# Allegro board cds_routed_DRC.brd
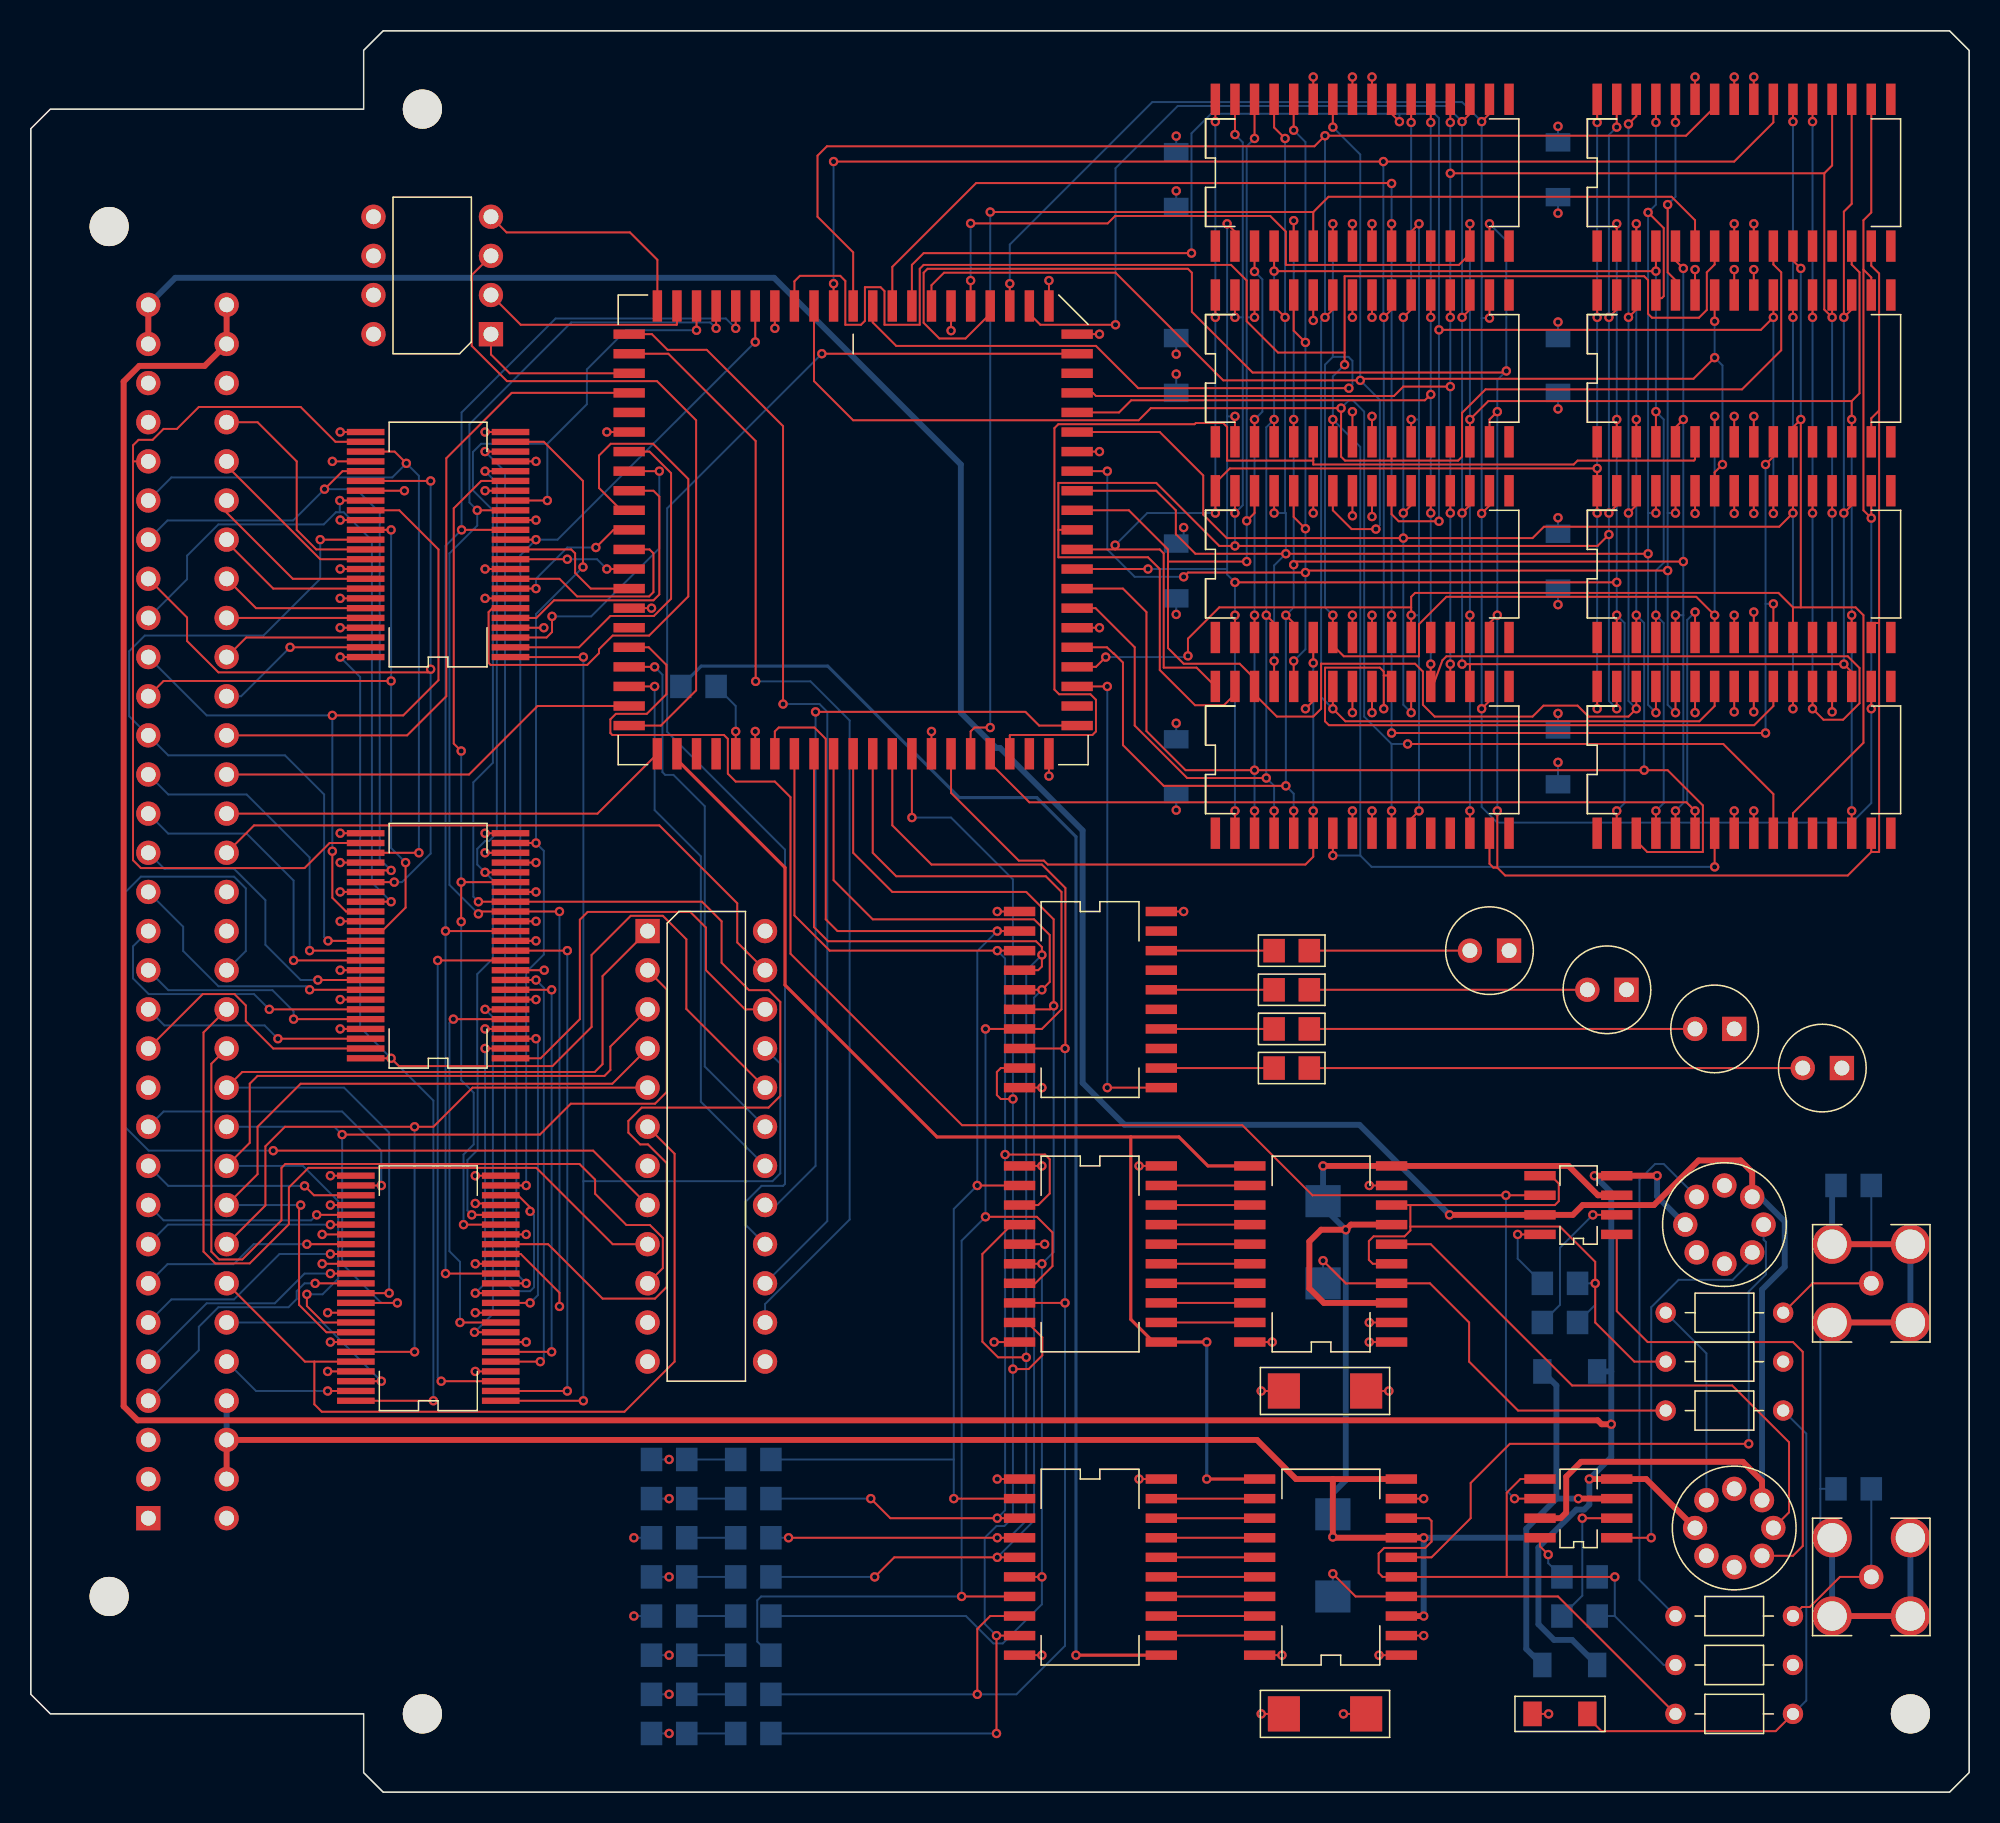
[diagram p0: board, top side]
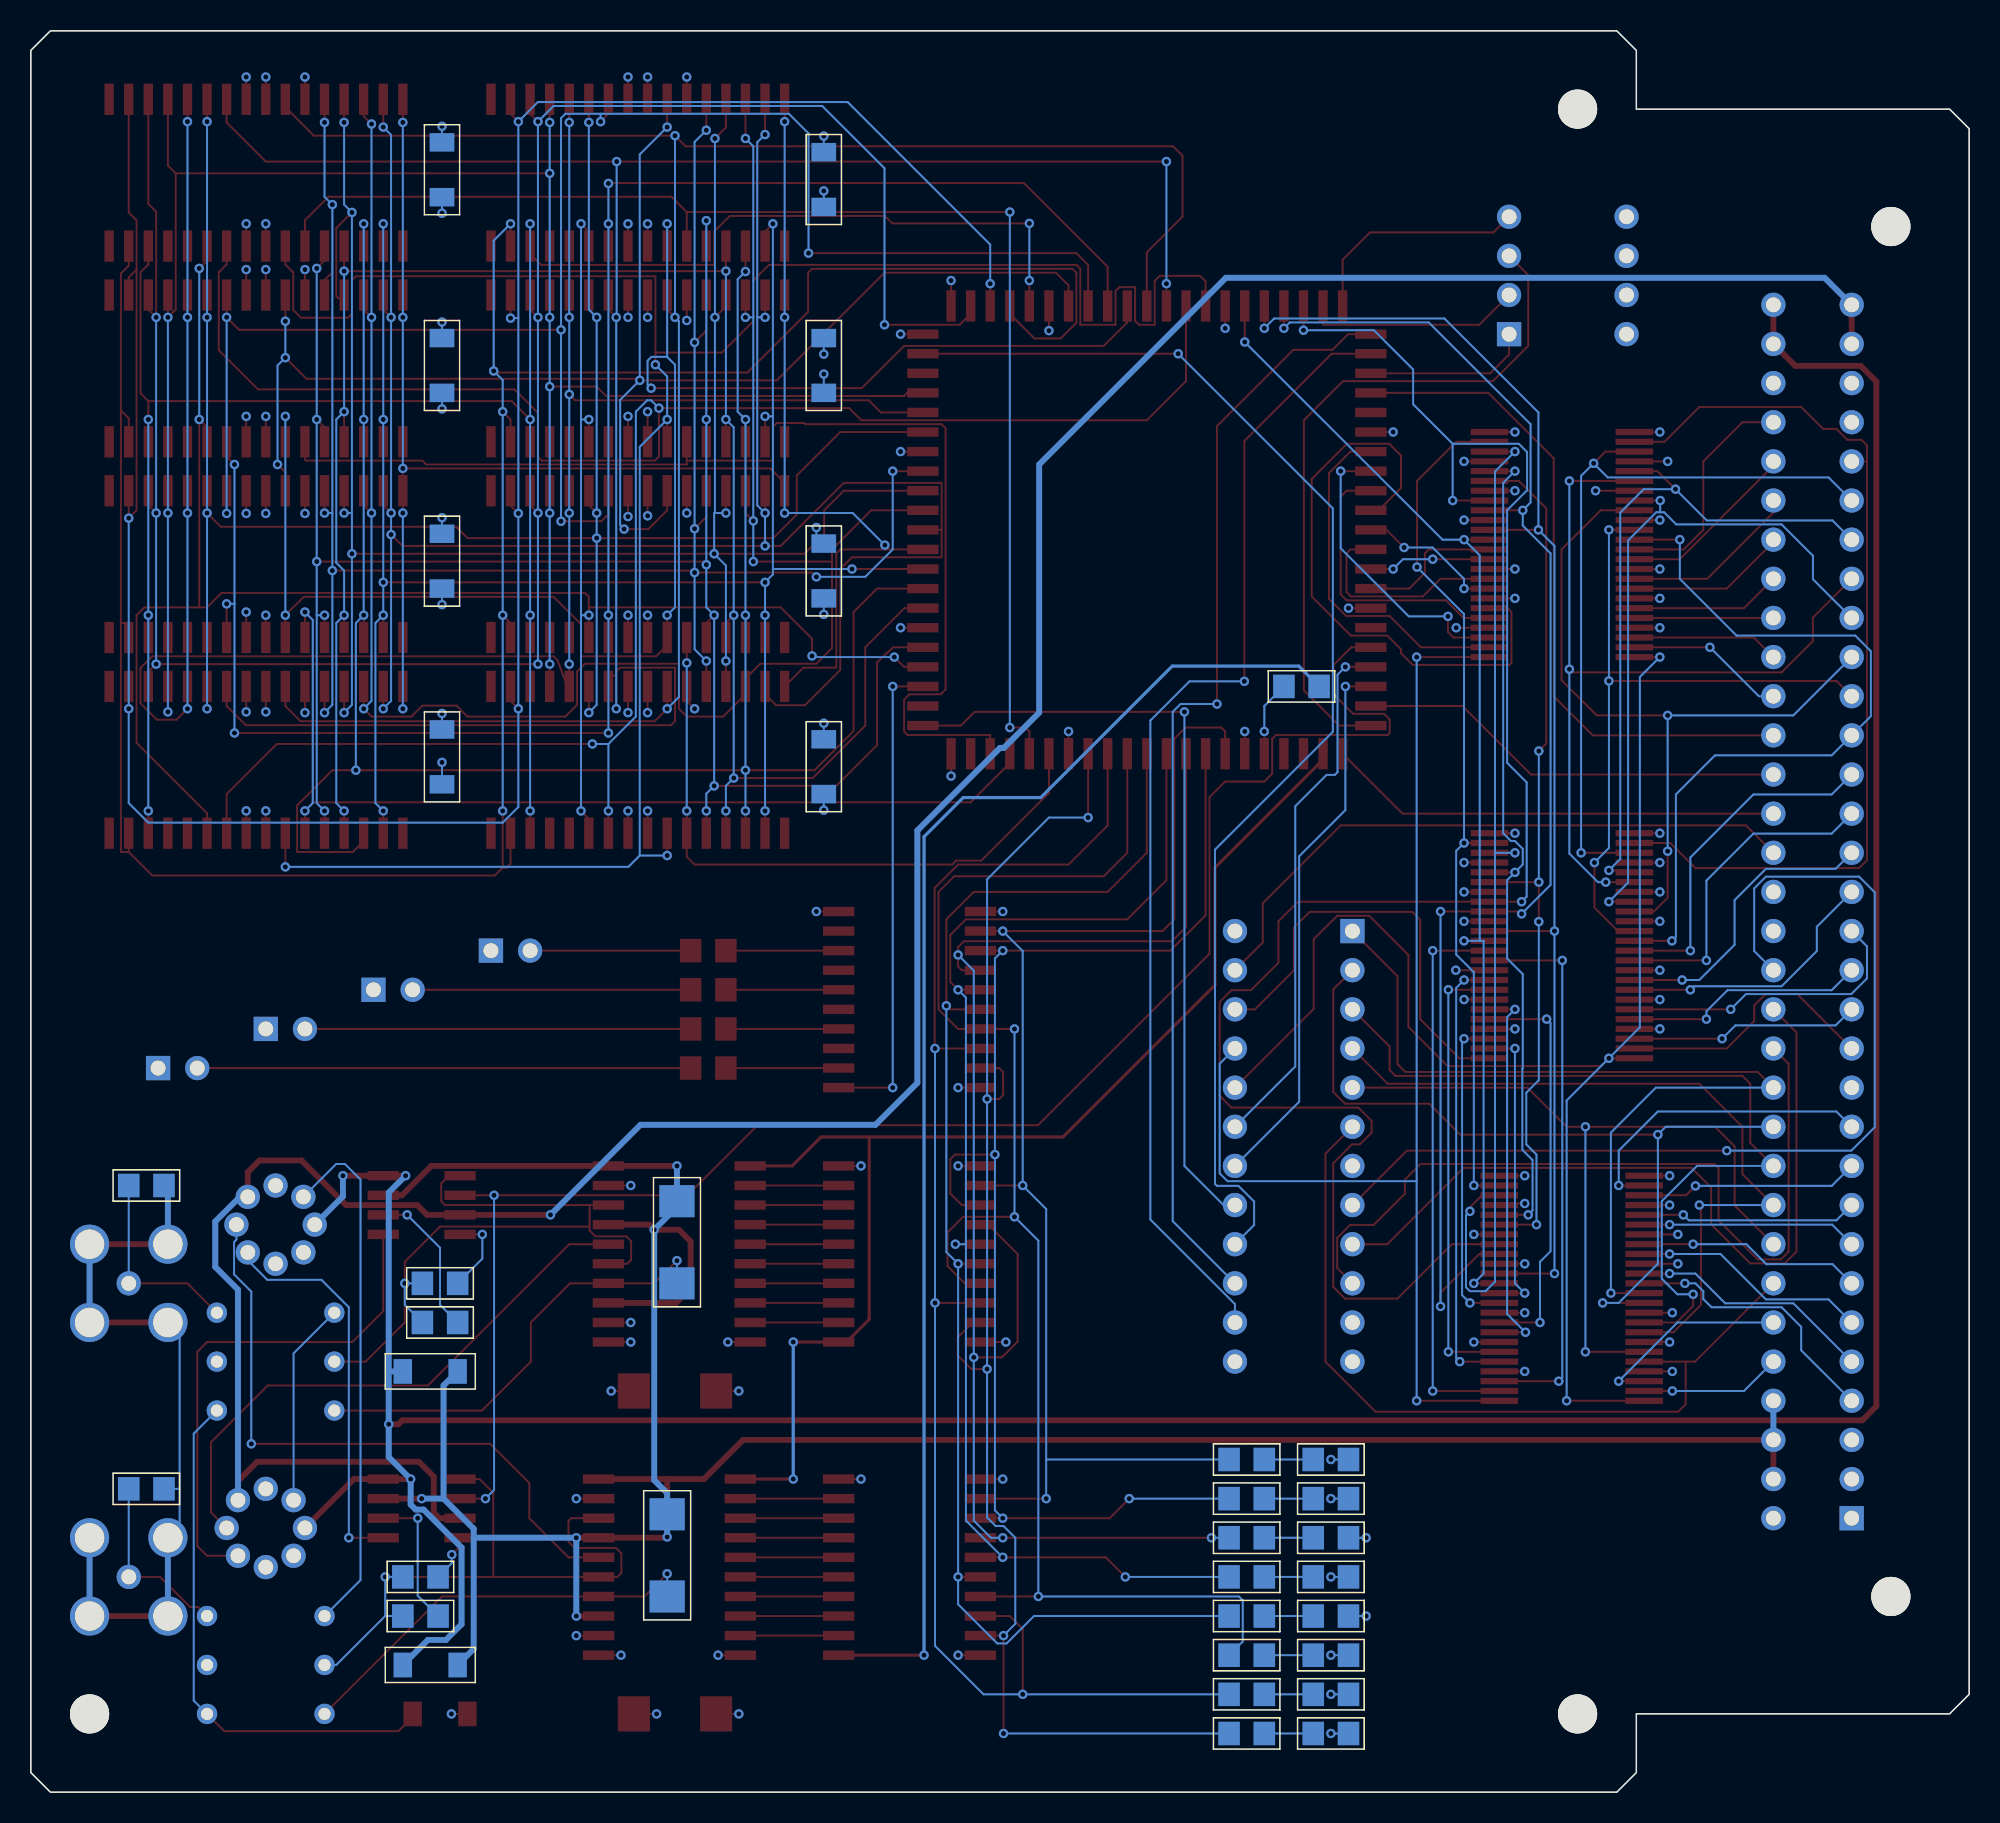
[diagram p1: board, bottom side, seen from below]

Outline 125.73 x 114.3 mm; copper layers: TOP, GND, VCC, BOTTOM. Coordinates in mm from the lower left corner of the outline.

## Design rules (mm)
constraint set DEFAULT: min track width 0.127
net group BNC2: nets BNC2 OUTA
net group BNC3: nets BNC3 OUTB
net group POD_B: nets POD_B+ POD_B-
net group Q1: nets Q0 Q1
net group Q3: nets Q2 Q3
net group Q5: nets Q4 Q5
net group Q7: nets Q6 Q7
net group VCLKC: nets N409523 VCLKC
net group VD0: nets N14855 VD0
net group VD1: nets N14853 VD1
net group VD2: nets N14849 VD2
net group VD3: nets N14843 VD3
net group VD4: nets N15161 VD4
net group VD5: nets N15155 VD5
net group VD6: nets N15151 VD6
net group VD7: nets N15143 VD7
net group N00038_DATA_DAAMP: nets N00038_DATA_DAAMP N00038_DATA_DAAMP0 VREF
net group SYNC: nets VCLKA
nets with their own width: min track width 0.254; nets AGND GND_EARTH V12N V+12

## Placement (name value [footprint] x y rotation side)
C5  47PF  [SM_0805]  119.38 39.37 180 bottom
C6  47PF  [SM_0805]  119.38 19.69 180 bottom
C7  3300  [SM_0805]  42.55 6.35 180 bottom
C8  3300  [SM_0805]  42.55 11.43 180 bottom
C9  3300  [SM_0805]  42.55 16.51 180 bottom
C10  3300  [SM_0805]  42.55 21.59 180 bottom
C11  3300  [SM_0805]  42.55 3.81 180 bottom
C12  3300  [SM_0805]  42.55 8.89 180 bottom
C13  3300  [SM_0805]  42.55 13.97 180 bottom
C14  3300  [SM_0805]  42.55 19.05 180 bottom
C15  0.1uF  [SM_1206]  99.06 103.5 90 bottom
C16  0.1uF  [SM_1206]  99.06 78.11 90 bottom
C17  0.1uF  [SM_1206]  99.06 90.8 90 bottom
C18  0.1uF  [SM_1206]  74.3 102.87 90 bottom
C19  0.1uF  [SM_1206]  99.06 65.41 90 bottom
C20  0.1uF  [SM_1206]  74.3 90.8 90 bottom
C21  0.1uF  [SM_1206]  74.3 77.47 90 bottom
C22  0.1uF  [SM_1206]  74.3 64.77 90 bottom
C23  .01uF  [SMC_6032]  81.28 26.03 0 top
C24  .01uF  [SMC_6032]  83.82 33.02 90 bottom
C25  0.1uF  [SM_1206]  101.6 27.3 180 bottom
C26  .01uF  [SMC_6032]  81.28 5.08 0 top
C27  .01uF  [SMC_6032]  84.45 12.7 90 bottom
C28  0.1uF  [SM_1206]  101.6 8.25 180 bottom
D1  -  [LED]  95.88 54.61 180 top
D2  -  [LED]  103.5 52.07 180 top
D3  -  [LED]  110.49 49.53 180 top
D4  -  [LED]  117.47 46.99 180 top
J1  CON64  [DIN64]  7.62 17.78 0 top
J2  -  [BNC]  119.38 33.02 0 top
J3  -  [BNC]  119.38 13.97 0 top
L1  50  [IND300]  106.04 31.12 0 top
L2  50  [IND300]  106.68 11.43 0 top
L3  50  [IND300]  113.66 24.77 180 top
L4  50  [IND300]  113.66 27.94 180 top
L5  50  [IND300]  114.3 5.08 180 top
L6  50  [IND300]  114.3 8.25 180 top
NOREF  -  [unnamed]  25.4 5.08 0 top
NOREF#2  -  [#2]  -30.48 -55.88 0 top
NOREF#3  -  [#2]  259.08 129.54 0 top
R1  150  [SM_0805]  80.64 54.61 0 top
R2  150  [SM_0805]  80.64 52.07 0 top
R3  150  [SM_0805]  80.64 49.53 0 top
R4  150  [SM_0805]  80.64 46.99 0 top
R5  2K  [SM_0805]  44.45 71.75 180 bottom
R6  10K  [SM_0805]  45.72 6.35 0 bottom
R7  10K  [SM_0805]  45.72 11.43 0 bottom
R8  10K  [SM_0805]  45.72 16.51 0 bottom
R9  10K  [SM_0805]  45.72 21.59 0 bottom
R10  10K  [SM_0805]  45.72 3.81 0 bottom
R11  10K  [SM_0805]  45.72 8.89 0 bottom
R12  10K  [SM_0805]  45.72 13.97 0 bottom
R13  10K  [SM_0805]  45.72 19.05 0 bottom
R14  1/4w  [SM_1206]  100.97 5.08 180 top
R15  100  [SM_0805]  100.33 30.48 180 bottom
R16  100  [SM_0805]  100.33 33.02 180 bottom
R17  100  [SM_0805]  101.6 13.97 180 bottom
R18  100  [SM_0805]  101.6 11.43 180 bottom
U1  FCT16245  [SOIC48]  30.48 25.4 180 top
U2  20L10  [DIP24]  40 55.88 0 top
U3  FCT16245  [SOIC48]  31.11 47.62 180 top
U4  FCT16245  [SOIC48]  31.11 73.66 180 top
U5  EPF8282A_LCC  [PLCC84]  53.34 81.91 180 top
U6  74ACT574  [SOIC20]  64.13 57.15 0 top
U7  EPC1064  [DIP8]  29.84 94.61 180 top
U8  74ACT574  [SOIC20]  64.13 40.64 0 top
U9  74ACT574  [SOIC20]  64.13 20.32 0 top
U10  TC55B4257  [SOIC32]  76.84 62.23 90 top
U11  TC55B4257  [SOIC32]  101.6 100.33 90 top
U12  TC55B4257  [SOIC32]  101.6 62.23 90 top
U13  TC55B4257  [SOIC32]  76.84 87.63 90 top
U14  TC55B4257  [SOIC32]  76.84 74.93 90 top
U15  TC55B4257  [SOIC32]  76.84 100.33 90 top
U16  TC55B4257  [SOIC32]  101.6 74.93 90 top
U17  TC55B4257  [SOIC32]  101.6 87.63 90 top
U18  TLC5602A  [SOIC20]  88.27 29.21 180 top
U19  DG419AK  [SOIC8]  102.87 36.2 180 top
U20  TLE2037A  [TO-99]  110.49 17.14 0 top
U21  TLC5602A  [SOIC20]  88.9 8.89 180 top
U22  TLE2037A  [TO-99]  109.85 36.83 0 top
U23  DG419AK  [SOIC8]  102.87 16.51 180 top

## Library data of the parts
C5 C23 C24 = CAP: room: CHAN1
C6 C26 C27 = CAP: room: CHAN2
C7-C14 = CAP
C15-C22 = CAP NP: room: MEM
C25 = CAP NP: room: CHAN1
C28 = CAP NP: room: CHAN2
D1-D4 = PHOTODIODE
J1 = CON64
J2 = BNC: room: CHAN1
J3 = BNC: room: CHAN2
L1 L3 L4 = INDUCTOR: room: CHAN1
L2 L5 L6 = INDUCTOR: room: CHAN2
R1-R4 = R: room: LED
R5-R13 = R
R14 R17 R18 = R: room: CHAN2
R15 R16 = R: room: CHAN1
U1 U3 U4 = FCT16245
U2 = 20L10: alternate symbols: (T:SOIC24;B:SOIC24_PE)
U5 = EPF8282A/LCC
U6 = 74ACT574: alternate symbols: (TSSOP20;DIP20); room: LED
U7 = EPC1064
U8 = 74ACT574: alternate symbols: (TSSOP20;DIP20); room: CHAN1
U9 = 74ACT574: alternate symbols: (TSSOP20;DIP20); room: CHAN2
U10-U17 = TC55B4257: room: MEM
U18 = TLC5602A: room: CHAN1
U19 = DG419AK: room: CHAN1
U20 = TLE2037A: room: CHAN1
U21 = TLC5602A: room: CHAN2
U22 = TLE2037A: room: CHAN2
U23 = DG419AK: room: CHAN2

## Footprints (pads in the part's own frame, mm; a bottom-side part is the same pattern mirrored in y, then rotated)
BNC
  round 1.575 hole 0.965: 1(0,0)
  round 2.54 hole 1.905: 2(-2.54,2.54) 3(-2.54,-2.54) 4(2.54,2.54) 5(2.54,-2.54)
DIN64
  round 2.54 hole 2.794 unplated: (-2.54,83.82) (-2.54,-5.08)
  rect 1.575x1.575 hole 0.965: 1(0,0)
  round 1.575 hole 0.965: 2(0,2.54) 3(0,5.08) 4(0,7.62) 5(0,10.16) 6(0,12.7) 7(0,15.24) 8(0,17.78) 9(0,20.32) 10(0,22.86) 11(0,25.4) 12(0,27.94) 13(0,30.48) 14(0,33.02) 15(0,35.56) 16(0,38.1) 17(0,40.64) 18(0,43.18) 19(0,45.72) 20(0,48.26) 21(0,50.8) 22(0,53.34) 23(0,55.88) 24(0,58.42) 25(0,60.96) 26(0,63.5) 27(0,66.04) 28(0,68.58) 29(0,71.12) 30(0,73.66) 31(0,76.2) 32(0,78.74) 33(5.08,0) 34(5.08,2.54) 35(5.08,5.08) 36(5.08,7.62) 37(5.08,10.16) 38(5.08,12.7) 39(5.08,15.24) 40(5.08,17.78) 41(5.08,20.32) 42(5.08,22.86) 43(5.08,25.4) 44(5.08,27.94) 45(5.08,30.48) 46(5.08,33.02) 47(5.08,35.56) 48(5.08,38.1) 49(5.08,40.64) 50(5.08,43.18) 51(5.08,45.72) 52(5.08,48.26) 53(5.08,50.8) 54(5.08,53.34) 55(5.08,55.88) 56(5.08,58.42) 57(5.08,60.96) 58(5.08,63.5) 59(5.08,66.04) 60(5.08,68.58) 61(5.08,71.12) 62(5.08,73.66) 63(5.08,76.2) 64(5.08,78.74)
DIP8
  rect 1.575x1.575 hole 0.965: 1(0,0)
  round 1.575 hole 0.965: 2(0,-2.54) 3(0,-5.08) 4(0,-7.62) 5(7.62,-7.62) 6(7.62,-5.08) 7(7.62,-2.54) 8(7.62,0)
DIP24
  rect 1.575x1.575 hole 0.965: 1(0,0)
  round 1.575 hole 0.965: 2(0,-2.54) 3(0,-5.08) 4(0,-7.62) 5(0,-10.16) 6(0,-12.7) 7(0,-15.24) 8(0,-17.78) 9(0,-20.32) 10(0,-22.86) 11(0,-25.4) 12(0,-27.94) 13(7.62,-27.94) 14(7.62,-25.4) 15(7.62,-22.86) 16(7.62,-20.32) 17(7.62,-17.78) 18(7.62,-15.24) 19(7.62,-12.7) 20(7.62,-10.16) 21(7.62,-7.62) 22(7.62,-5.08) 23(7.62,-2.54) 24(7.62,0)
IND300
  round 1.321 hole 0.787: 1(0,0) 2(7.62,0)
LED
  rect 1.575x1.575 hole 0.965: 1(0,0)
  round 1.575 hole 0.965: 2(2.54,0)
PLCC84
  rect 0.61x2.032 smd: 1(0,-14.529) 2(1.27,-14.529) 3(2.54,-14.529) 4(3.81,-14.529) 5(5.08,-14.529) 6(6.35,-14.529) 7(7.62,-14.529) 8(8.89,-14.529) 9(10.16,-14.529) 10(11.43,-14.529) 11(12.7,-14.529) 33(12.7,14.529) 34(11.43,14.529) 35(10.16,14.529) 36(8.89,14.529) 37(7.62,14.529) 38(6.35,14.529) 39(5.08,14.529) 40(3.81,14.529) 41(2.54,14.529) 42(1.27,14.529) 43(0,14.529) 44(-1.27,14.529) 45(-2.54,14.529) 46(-3.81,14.529) 47(-5.08,14.529) 48(-6.35,14.529) 49(-7.62,14.529) 50(-8.89,14.529) 51(-10.16,14.529) 52(-11.43,14.529) 53(-12.7,14.529) 75(-12.7,-14.529) 76(-11.43,-14.529) 77(-10.16,-14.529) 78(-8.89,-14.529) 79(-7.62,-14.529) 80(-6.35,-14.529) 81(-5.08,-14.529) 82(-3.81,-14.529) 83(-2.54,-14.529) 84(-1.27,-14.529)
  rect 2.032x0.61 smd: 12(14.529,-12.7) 13(14.529,-11.43) 14(14.529,-10.16) 15(14.529,-8.89) 16(14.529,-7.62) 17(14.529,-6.35) 18(14.529,-5.08) 19(14.529,-3.81) 20(14.529,-2.54) 21(14.529,-1.27) 22(14.529,0) 23(14.529,1.27) 24(14.529,2.54) 25(14.529,3.81) 26(14.529,5.08) 27(14.529,6.35) 28(14.529,7.62) 29(14.529,8.89) 30(14.529,10.16) 31(14.529,11.43) 32(14.529,12.7) 54(-14.529,12.7) 55(-14.529,11.43) 56(-14.529,10.16) 57(-14.529,8.89) 58(-14.529,7.62) 59(-14.529,6.35) 60(-14.529,5.08) 61(-14.529,3.81) 62(-14.529,2.54) 63(-14.529,1.27) 64(-14.529,0) 65(-14.529,-1.27) 66(-14.529,-2.54) 67(-14.529,-3.81) 68(-14.529,-5.08) 69(-14.529,-6.35) 70(-14.529,-7.62) 71(-14.529,-8.89) 72(-14.529,-10.16) 73(-14.529,-11.43) 74(-14.529,-12.7)
SM_0805
  rect 1.397x1.524 smd: 1(0,0) 2(2.286,0)
SM_1206
  rect 1.194x1.6 smd: 1(0,0) 2(3.556,0)
SMC_6032
  rect 2.083x2.286 smd: 1(0,0) 2(5.334,0)
SOIC8
  rect 2.032x0.61 smd: 1(0,0) 2(0,-1.27) 3(0,-2.54) 4(0,-3.81) 5(4.978,-3.81) 6(4.978,-2.54) 7(4.978,-1.27) 8(4.978,0)
SOIC20
  rect 2.032x0.61 smd: 1(0,0) 2(0,-1.27) 3(0,-2.54) 4(0,-3.81) 5(0,-5.08) 6(0,-6.35) 7(0,-7.62) 8(0,-8.89) 9(0,-10.16) 10(0,-11.43) 11(9.195,-11.43) 12(9.195,-10.16) 13(9.195,-8.89) 14(9.195,-7.62) 15(9.195,-6.35) 16(9.195,-5.08) 17(9.195,-3.81) 18(9.195,-2.54) 19(9.195,-1.27) 20(9.195,0)
SOIC32
  rect 2.032x0.61 smd: 1(0,0) 2(0,-1.27) 3(0,-2.54) 4(0,-3.81) 5(0,-5.08) 6(0,-6.35) 7(0,-7.62) 8(0,-8.89) 9(0,-10.16) 10(0,-11.43) 11(0,-12.7) 12(0,-13.97) 13(0,-15.24) 14(0,-16.51) 15(0,-17.78) 16(0,-19.05) 17(9.525,-19.05) 18(9.525,-17.78) 19(9.525,-16.51) 20(9.525,-15.24) 21(9.525,-13.97) 22(9.525,-12.7) 23(9.525,-11.43) 24(9.525,-10.16) 25(9.525,-8.89) 26(9.525,-7.62) 27(9.525,-6.35) 28(9.525,-5.08) 29(9.525,-3.81) 30(9.525,-2.54) 31(9.525,-1.27) 32(9.525,0)
SOIC48
  rect 2.438x0.406 smd: 1(0,0) 2(0,-0.635) 3(0,-1.27) 4(0,-1.905) 5(0,-2.54) 6(0,-3.175) 7(0,-3.81) 8(0,-4.445) 9(0,-5.08) 10(0,-5.715) 11(0,-6.35) 12(0,-6.985) 13(0,-7.62) 14(0,-8.255) 15(0,-8.89) 16(0,-9.525) 17(0,-10.16) 18(0,-10.795) 19(0,-11.43) 20(0,-12.065) 21(0,-12.7) 22(0,-13.335) 23(0,-13.97) 24(0,-14.605) 25(9.398,-14.605) 26(9.398,-13.97) 27(9.398,-13.335) 28(9.398,-12.7) 29(9.398,-12.065) 30(9.398,-11.43) 31(9.398,-10.795) 32(9.398,-10.16) 33(9.398,-9.525) 34(9.398,-8.89) 35(9.398,-8.255) 36(9.398,-7.62) 37(9.398,-6.985) 38(9.398,-6.35) 39(9.398,-5.715) 40(9.398,-5.08) 41(9.398,-4.445) 42(9.398,-3.81) 43(9.398,-3.175) 44(9.398,-2.54) 45(9.398,-1.905) 46(9.398,-1.27) 47(9.398,-0.635) 48(9.398,0)
TO-99
  round 1.575 hole 0.965: 1(0,-2.54) 2(1.803,-1.803) 3(2.54,0) 4(1.803,1.803) 5(0,2.54) 6(-1.803,1.803) 7(-2.54,0) 8(-1.803,-1.803)
unnamed
  round 2.54 hole 2.794 unplated: (0,104.14) (0,0) (96.52,0)

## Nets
AGND: C24.2 C25.2 C27.2 C28.2 J1.34 J1.35 J1.36 U18.3 U18.7 U18.10 U19.3 U21.3 U21.7 U21.10 U23.3
GND: C7.2 C8.2 C9.2 C10.2 C11.2 C12.2 C13.2 C14.2 C15.2 C16.2 C17.2 C18.2 C19.2 C20.2 C21.2 C22.2 C23.2 C26.2 J1.1 J1.2 J1.3 J1.33 R14.2 U1.4 U1.10 U1.15 U1.21 U1.24 U1.25(\G\\\) U1.28 U1.34 U1.39 U1.45 U2.11 U2.12 U2.13 U3.4 U3.10 U3.15 U3.21 U3.24 U3.25(\G\\\) U3.28 U3.34 U3.39 U3.45 U4.4 U4.10 U4.15 U4.21 U4.24 U4.25(\G\\\) U4.28 U4.34 U4.39 U4.45 U5.5 U5.26 U5.47 U5.53 U5.68 U5.74 U5.75 U6.1 U6.10 U7.5 U8.1 U8.10 U9.1 U9.10 U10.9 U10.25 U10.27 U11.9 U11.25 U11.27 U12.9 U12.25 U12.27 U13.9 U13.25 U13.27 U14.9 U14.25 U14.27 U15.9 U15.25 U15.27 U16.9 U16.25 U16.27 U17.9 U17.25 U17.27 U18.1 U18.20 U21.1 U21.20
GND_EARTH: C5.2 C6.2 J2.2 J2.3 J2.4 J2.5(\GND5\) J3.2 J3.3 J3.4 J3.5(\GND5\)
V12N: J1.31 J1.32 U19.7 U20.4(\V-\) U22.4(\V-\) U23.7
VCC: C15.1 C16.1 C17.1 C18.1 C19.1 C20.1 C21.1 C22.1 C23.1 C26.1 D1.1 D2.1 D3.1 D4.1 J1.29 J1.30 J1.62 L4.1 L6.1 U1.7 U1.18 U1.31 U1.42 U2.24(\VCC\) U3.7 U3.18 U3.31 U3.42 U4.7 U4.18 U4.31 U4.42 U5.17 U5.38 U5.59 U5.80 U6.20 U7.7 U7.8 U8.20 U9.20 U10.8 U10.24 U11.8 U11.24 U12.8 U12.24 U13.8 U13.24 U14.8 U14.24 U15.8 U15.24 U16.8 U16.24 U17.8 U17.24 U18.2 U18.9(\VD2\) U21.2 U21.9(\VD2\)
A0: J1.54 U4.47
A1: J1.55 U4.46
A2: J1.56 U4.44
A3: J1.57 U4.43
A4: J1.58 U4.41
A5: J1.59 U4.40
A6: J1.60 U4.38
A7: J1.61 U4.37
A8: J1.13 U3.47
A9: J1.14 U3.46
A10: J1.15 U3.44
A11: J1.16 U3.43
A12: J1.17 U3.41
A13: J1.18 U3.40
A14: J1.19 U3.38
A15: J1.20 U3.37
A16: J1.37 U1.47
A17: J1.38 U1.46
A18: J1.39 U1.44 U2.6
A19: J1.40 U1.43 U2.5
A20: J1.41 U1.41 U2.4
A21: J1.42 U1.40 U2.3
A22: J1.43 U1.38 U2.2
A23: J1.44 U1.37 U2.1
AEN: J1.47 U2.8
BA0: U1.13 U3.13 U4.13 U5.6
BA1: U1.14 U3.14 U4.14 U5.7
BA2: U1.16 U3.16 U4.16 U5.8
BA3: U1.17 U3.17 U4.17 U5.9
BA4: U1.19 U3.19 U4.19
BA5: U1.20 U3.20 U4.20
BA6: U1.22 U3.22 U4.22
BA7: U1.23 U3.23 U4.23
BD0: U4.12 U5.25
BD1: U4.11 U5.24
BD2: U4.9 U5.23
BD3: U4.8 U5.22
BD4: U4.6 U5.21
BD5: U4.5 U5.20
BD6: U4.3 U5.19
BD7: U4.2 U5.18
BD8: U1.12 U3.2
BD9: U1.11 U3.3
BD10: U1.9 U3.5
BD11: U1.8 U3.6
BD12: U1.6 U3.8
BD13: U1.5 U3.9
BD14: U1.3 U3.11
BD15: U1.2 U3.12
BNC2: C5.1 J2.1 L1.2
BNC3: C6.1 J3.1 L2.2
BRD: U2.16 U5.73
BRESET: U2.15 U5.12
BWR: U2.17 U5.54
D0: J1.28 U3.26 U4.26
D1: J1.27 U3.27 U4.27
D2: J1.26 U3.29 U4.29
D3: J1.25 U3.30 U4.30
D4: J1.24 U3.32 U4.32
D5: J1.23 U3.33 U4.33
D6: J1.22 U3.35 U4.35
D7: J1.21 U3.36 U4.36
DATA: U5.14 U7.1
DCLK: U5.10 U7.2
DDIR: U1.48 U2.20 U3.48 U4.48
DEN: U1.1 U2.21 U4.1
DHEN: U2.22 U3.1
FPGA: U2.18 U5.30
GAIN: U5.28 U19.6 U23.6
HS: U2.19 U5.29
MCLK: J1.52 U5.31
MRD: J1.46 U2.9
MWR: J1.45 U2.10
N00036_DATA_DAAMP: L4.2 R15.1 R16.1 U18.5 U18.8 U19.5(\VL\)
N00036_DATA_DAAMP0: L6.2 R17.1 R18.1 U21.5 U21.8 U23.5(\VL\)
N00038_DATA_DAAMP: C24.1 L3.2 U18.4
N00038_DATA_DAAMP0: C27.1 L5.2 U21.4
N00044_DATA_DAAMP: U19.1 U20.2
N00044_DATA_DAAMP0: U22.2 U23.1
N00060_DATA_DAAMP: U18.6 U20.3
N00060_DATA_DAAMP0: U21.6 U22.3
N282866_DATA_DAAMP: R16.2 U19.8
N282866_DATA_DAAMP0: R17.2 U23.8
N282912_DATA_DAAMP: R15.2 U19.2
N282912_DATA_DAAMP0: R18.2 U23.2
NCS: U5.11 U7.4
OE: U5.32 U7.3(\OE\)
OUTA: L1.1 U20.6
OUTB: L2.1 U22.6
POD_A+: J1.11 U1.26
POD_A-: J1.10 U1.27
POD_B+: J1.9 U1.29
POD_B-: J1.8 U1.30
POD_C+: J1.7 U1.32
POD_C-: J1.6 U1.33
POD_D+: J1.5 U1.35
POD_D-: J1.4 U1.36
Q0: R4.1 U6.12(\Q8\)
Q1: D4.2(\CATHODE\) R4.2
Q2: R3.1 U6.14
Q3: D3.2(\CATHODE\) R3.2
Q4: R2.1 U6.16
Q5: D2.2(\CATHODE\) R2.2
Q6: R1.1 U6.18
Q7: D1.2(\CATHODE\) R1.2
RA0: U5.58 U10.5 U11.5 U12.5 U13.5 U14.5 U15.5 U16.5 U17.5
RA1: U5.60 U10.4 U11.4 U12.4 U13.4 U14.4 U15.4 U16.4 U17.4
RA2: U5.61 U10.3 U11.3 U12.3 U13.3 U14.3 U15.3 U16.3 U17.3
RA3: U5.62 U10.2 U11.2 U12.2 U13.2 U14.2 U15.2 U16.2 U17.2
RA4: U5.63 U10.32 U11.32 U12.32 U13.32 U14.32 U15.32 U16.32 U17.32
RA5: U5.64 U10.31 U11.31 U12.31 U13.31 U14.31 U15.31 U16.31 U17.31
RA6: U5.65 U10.30 U11.30 U12.30 U13.30 U14.30 U15.30 U16.30 U17.30
RA7: U5.66 U10.29 U11.29 U12.29 U13.29 U14.29 U15.29 U16.29 U17.29
RA8: U5.67 U10.28 U11.28 U12.28 U13.28 U14.28 U15.28 U16.28 U17.28
RA9: U5.69 U10.22 U11.22 U12.22 U13.22 U14.22 U15.22 U16.22 U17.22
RA10: U5.70 U10.21 U11.21 U12.21 U13.21 U14.21 U15.21 U16.21 U17.21
RA11: U5.71 U10.20 U11.20 U12.20 U13.20 U14.20 U15.20 U16.20 U17.20
RA12: U5.76 U10.19 U11.19 U12.19 U13.19 U14.19 U15.19 U16.19 U17.19
RA13: U5.77 U10.18 U11.18 U12.18 U13.18 U14.18 U15.18 U16.18 U17.18
RA14: U5.78 U10.15 U11.15 U12.15 U13.15 U14.15 U15.15 U16.15 U17.15
RA15: U5.79 U10.14 U11.14 U12.14 U13.14 U14.14 U15.14 U16.14 U17.14
RCS0: U5.48 U10.6 U14.6
RCS1: U5.49 U11.6 U15.6
RCS2: U5.50 U12.6 U16.6
RCS3: U5.51 U13.6 U17.6
RD0: U5.81 U14.26 U15.26 U16.26 U17.26
RD1: U5.82 U14.23 U15.23 U16.23 U17.23
RD2: U5.83 U14.10 U15.10 U16.10 U17.10
RD3: U5.84 U14.7 U15.7 U16.7 U17.7
RD4: U5.1 U10.26 U11.26 U12.26 U13.26
RD5: U5.2 U10.23 U11.23 U12.23 U13.23
RD6: U5.3 U10.10 U11.10 U12.10 U13.10
RD7: U5.4 U10.7 U11.7 U12.7 U13.7
RDY: J1.50 U2.23
RESET: J1.53 U5.15
RWE: U5.57 U10.11(\W\\E\\\) U11.11(\W\\E\\\) U12.11(\W\\E\\\) U13.11(\W\\E\\\) U14.11(\W\\E\\\) U15.11(\W\\E\\\) U16.11(\W\\E\\\) U17.11(\W\\E\\\)
SEL: U2.14 U5.13
V+12: C25.1 C28.1 J1.63 J1.64 U19.4 U20.7 U22.7 U23.4
VCLKA: U5.34 U8.11 U18.11 U21.11
VCLKC: R5.2 U9.11
VD0: R9.2 U5.39 U6.2 U8.2 U9.2
VD1: R13.2 U5.40 U6.3 U8.3 U9.3
VD2: R8.2 U5.41 U6.4 U8.4 U9.4
VD3: R12.2 U5.42 U6.5 U8.5 U9.5
VD4: R7.2 U5.43 U6.6 U8.6 U9.6
VD5: R11.2 U5.44 U6.7 U8.7 U9.7
VD6: R6.2 U5.45 U6.8 U8.8 U9.8
VD7: R10.2 U5.46(\VD7\) U6.9 U8.9 U9.9
VREF: L3.1 L5.1 R14.1
WAIT: J1.51 U5.33
WSTAT: U5.56 U6.11
N14843: C13.1 R12.1
N14849: C9.1 R8.1
N14853: C14.1 R13.1
N14855: C10.1 R9.1
N15143: C11.1 R10.1
N15151: C7.1 R6.1
N15155: C12.1 R11.1
N15161: C8.1 R7.1
N58063: U8.19 U18.12
N58118: U8.18 U18.13
N58173: U8.17 U18.14
N58228: U8.16 U18.15
N58283: U8.15 U18.16
N58338: U8.14 U18.17
N58393: U8.13 U18.18
N58448: U8.12(\Q8\) U18.19
N58834: U9.19 U21.12
N58889: U9.18 U21.13
N58944: U9.17 U21.14
N58999: U9.16 U21.15
N59054: U9.15 U21.16
N59109: U9.14 U21.17
N59164: U9.13 U21.18
N59219: U9.12(\Q8\) U21.19
N409523: R5.1 U5.37

Pads without a net: J1 12 48 49; U2 7; U5 16 27 35 36 52 55 72; U6 13 15 17 19; U7 6; U10 1 12 13 16 17; U11 1 12 13 16 17; U12 1 12 13 16 17; U13 1 12 13 16 17; U14 1 12 13 16 17; U15 1 12 13 16 17; U16 1 12 13 16 17; U17 1 12 13 16 17; U20 1 5 8; U22 1 5 8

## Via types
v1: diameter 0.61, hole 0.33, TOP to BOTTOM, 498 vias

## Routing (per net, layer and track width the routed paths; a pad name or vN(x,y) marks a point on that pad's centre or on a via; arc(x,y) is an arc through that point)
AGND: length 189.2
  TOP w0.381: U18.7 85.62,36.83 v1(85.29,36.5) 83.69,36.5 82.93,35.74 82.93,32.69 83.87,31.75 U18.3 ; 84.45,20.32 82.07,20.32 79.53,22.86 J1.35 J1.34 ; 84.45,20.32 U21.10 ; 84.45,20.32 v1(84.45,16.56) 84.51,16.51 U21.7 v1(90.35,16.51) ; U19.3 101.65,38.73 99.75,40.64 U18.10 v1(83.82,40.64) ; U21.3 v1(90.35,11.43) ; U23.3 v1(100.38,19.05)
  BOTTOM w0.381: C28.2 97,9.3 97,16.51 ; 98.96,19.05 97,17.09 97,16.51 ; 98.96,19.05 98.96,26.39 C25.2 ; 98.96,19.05 v1(100.38,19.05) ; J1.36 J1.35 ; v1(83.82,40.64) C24.2 83.82,37.97 v1(85.29,36.5) 85.29,20.24 84.45,19.41 C27.2 v1(84.45,16.56) ; v1(90.35,11.43) v1(90.35,16.51) 97,16.51
GND: length 135.8
  TOP w0.127: U5.5 v1(48.26,95) ; U18.1 v1(86.82,29.21) ; C26.2 v1(85.14,5.08) ; U1.15 v1(28.83,34.29) ; 21.72,86.36 v1(19.56,86.36) ; 21.72,53.34 v1(20.07,53.34) ; 21.72,88.27 v1(20.07,88.27) ; R14.2 v1(98.45,5.08) ; 83.19,71.75 83.19,70.82 v1(82.68,70.31) ; U1.4 v1(28.83,27.3) ; U16.27 v1(107.95,82.98) ; U4.15 v1(32.77,82.55) ; U3.10 v1(33.3,53.34) ; U1.24 v1(28.83,40) ; 21.72,82.55 v1(20.07,82.55) ; U13.25 v1(85.72,95.71) ; U21.20 v1(81.15,8.89) ; U1.45 v1(19.25,27.3) ; 83.19,97.16 v1(83.19,95.5) ; U17.9 v1(111.76,89.28) ; U6.1 v1(62.69,57.15) ; U1.34 v1(18.9,34.29) ; U17.25 v1(110.49,98.81) ; U21.1 v1(87.45,8.89) ; U1.10 v1(28.83,31.12) ; 21.72,62.23 v1(20.07,62.23) ; U4.21 v1(32.77,86.36) ; U10.9 v1(87,63.68) ; 67.87,87 v1(69.32,87) ; 83.19,109.86 v1(83.19,111.3) ; U12.25 v1(110.49,70.1) ; U8.10 v1(62.48,29.21) ; U3.15 v1(32.77,56.52) ; 21.72,79.38 v1(20.07,79.38) ; 21.72,60.32 v1(20.07,60.32) ; U14.25 v1(85.72,82.83) ; U12.9 v1(111.76,63.68) ; U1.39 v1(19.25,31.12) ; U17.27 v1(107.95,98.81) ; U6.10 v1(65.58,45.72) ; C23.2 v1(88.09,26.03) ; U5.47 v1(58.42,68.83) ; U5.26 v1(40.26,76.83) ; U15.25 v1(85.72,111.3) ; U12.27 v1(107.95,70.05) ; 83.19,84.45 v1(83.19,83.01) ; U5.74 v1(69.32,94.61) ; U9.10 v1(65.58,8.89) ; U10.25 v1(85.72,70.05) ; v1(28.83,38.2) 30.38,38.2 U1.21 ; U5.53 v1(66.04,65.94) ; U13.9 v1(87,89.28) ; U1.28 v1(19.43,38.1) ; U4.10 v1(29.46,79.38) ; U16.9 v1(111.76,76.58) ; U9.1 v1(62.69,20.32) ; U11.27 v1(107.95,111.3) ; U15.9 v1(87,101.78) ; U1.25 v1(19.43,40) ; U11.25 v1(110.49,111.3) ; U3.24 v1(29.46,62.23) ; U8.1 v1(65.58,40.64) ; U18.20 v1(80.52,29.21) ; U4.4 v1(33.27,75.56) ; U14.9 v1(87,76.38) ; U16.25 v1(110.49,82.98) ; 31.11,60.32 v1(32.77,60.32) ; 21.72,56.52 v1(20.07,56.52) ; U5.75 v1(66.04,98.09) ; U11.9 v1(111.76,101.78) ; 21.72,49.53 v1(20.07,49.53) ; 21.72,75.56 v1(20.07,75.56) ; U3.4 v1(29.46,49.53) ; U4.24 v1(29.46,88.27)
  BOTTOM w0.127: C7.2 v1(41.4,6.35) ; C21.2 74.78,81.51 v1(74.78,82.07) ; C10.2 v1(41.4,21.59) ; C22.2 v1(74.3,69.37) ; C19.2 v1(99.06,70) ; C20.2 v1(74.3,93.32) ; C15.2 v1(99.06,108.1) ; C14.2 v1(41.4,19.05) ; C9.2 v1(39.12,16.51) ; C16.2 v1(99.06,82.7) ; C11.2 v1(41.4,3.81) ; C17.2 v1(99.06,95.4) ; C12.2 v1(41.4,8.89) ; C13.2 v1(41.4,13.97) ; C18.2 v1(74.3,107.47) ; C8.2 v1(39.12,11.43)
GND_EARTH: length 50
  TOP w0.381: J3.3 J3.5 ; J2.4 J2.2 ; J2.3 J2.5
  BOTTOM w0.127: J3.2 116.08,17.27 116.08,19.69 ; 116.08,19.69 C6.2 ; 116.08,19.69 116.08,29.72 J2.3
  BOTTOM w0.381: J3.3 J3.2 ; J2.2 116.84,39.12 C5.2 ; J2.4 J2.5 ; J3.4 J3.5
V12N: length 195.4
  TOP w0.381: U22.4 111.66,40.23 110.9,41 108.18,41 105.28,38.1 100.66,38.1 100.03,37.46 U19.7 v1(92.02,37.46) ; J1.31 J1.32 ; U20.4 112.29,20.19 111.05,21.44 100.56,21.44 99.59,20.47 99.59,18.15 99.23,17.78 U23.7
  BOTTOM w0.381: J1.32 9.37,98.27 48.21,98.27 60.32,86.16 60.32,70.05 62.61,67.77 62.87,67.77 68.22,62.41 68.22,46.02 70.94,43.31 86.18,43.31 v1(92.02,37.46) ; U20.4 112.29,32.61 113.77,34.09 113.77,37.03 112.17,38.63 U22.4
VCC: length 73.9
  TOP w0.127: U10.8 v1(85.72,63.68) ; U1.31 v1(18.9,36.2) ; U1.18 v1(32.13,36.2) ; U5.38 v1(46.99,68.83) ; C26.1 v1(79.81,5.08) ; U12.8 v1(110.49,63.68) ; U13.8 v1(85.72,89.59) ; U11.24 v1(111.76,111.3) ; U8.20 v1(71.88,40.64) ; U9.20 v1(71.88,20.32) ; U14.24 v1(87,82.78) ; U1.42 v1(19.43,29.21) ; U17.24 v1(111.76,98.81) ; U4.18 v1(29.46,84.45) ; U14.8 v1(85.72,76.38) ; U15.8 v1(85.72,101.78) ; U16.8 v1(110.49,76.38) ; U16.24 v1(111.76,82.98) ; U18.9 v1(86.82,39.37) ; 21.72,77.47 v1(20.07,77.47) ; U21.9 v1(90.35,19.05) ; 21.72,51.43 v1(20.07,51.43) ; U3.18 v1(32.77,58.42) ; U17.8 v1(110.49,89.28) ; C23.1 v1(79.81,26.03) ; U11.8 v1(110.49,101.78) ; U10.24 v1(87,70.05) ; U15.24 v1(87,111.3) ; U6.20 v1(74.78,57.15) ; U4.7 v1(29.46,77.47) ; 21.72,84.45 v1(24.23,84.45) ; U5.17 v1(37.36,88.27) ; U13.24 v1(87,95.71) ; U3.7 v1(32.77,51.43) ; 21.72,58.42 v1(20.07,58.42) ; U1.7 v1(32.13,29.21) ; U5.80 v1(59.69,94.84) ; U18.2 v1(86.82,30.48) ; U5.59 v1(69.32,75.56) ; U21.2 v1(90.35,10.16) ; U12.24 v1(111.76,70.1)
  BOTTOM w0.127: C15.1 v1(99.06,102.46) ; C16.1 v1(99.06,77.06) ; C18.1 v1(74.3,103.91) ; C22.1 v1(74.3,63.73) ; C21.1 v1(74.3,76.43) ; C19.1 v1(99.06,66.83) ; C20.1 v1(74.3,92.02) ; C17.1 v1(99.06,89.76)
A0: length 10.3
  TOP w0.127: U4.47 v1(16.81,74.3)
  BOTTOM w0.127: J1.54 13.64,71.12 v1(16.81,74.3)
A1: length 9.5
  TOP w0.127: J1.55 13.97,74.93 U4.46
A2: length 9
  TOP w0.127: 21.72,76.2 J1.56
A3: length 9.8
  TOP w0.127: 21.72,76.83 14.6,76.83 J1.57
A4: length 10.4
  TOP w0.127: 21.72,78.11 15.72,78.11 12.7,81.13 J1.58
A5: length 11.6
  TOP w0.127: J1.59 12.7,83.03 16.99,78.74 21.72,78.74
A6: length 11.8
  TOP w0.127: J1.60 12.7,86.08 18.77,80.01 21.72,80.01
A7: length 15
  TOP w0.127: J1.61 14.71,88.9 17.25,86.36 17.25,81.91 18.52,80.64 21.72,80.64
A8: length 17.6
  TOP w0.127: J1.13 11.15,51.79 13.21,51.79 13.94,51.05 13.94,50.04 15.72,48.26 U3.47
A9: length 14.9
  TOP w0.127: U3.46 v1(16.03,48.89)
  BOTTOM w0.127: v1(16.03,48.89) 15.16,49.76 8.66,49.76 J1.14
A10: length 15.7
  TOP w0.127: 21.72,50.16 v1(17.04,50.16)
  BOTTOM w0.127: J1.15 8.92,52.04 15.67,52.04 17.04,50.67 v1(17.04,50.16)
A11: length 19.4
  TOP w0.127: 21.72,50.8 v1(15.47,50.8)
  BOTTOM w0.127: v1(15.47,50.8) 14.48,51.79 7.65,51.79 6.63,52.81 6.63,54.89 J1.16
A12: length 17.6
  TOP w0.127: 21.72,52.07 v1(18.08,52.07)
  BOTTOM w0.127: J1.17 9.88,56.16 9.88,54.58 12.17,52.3 17.86,52.3 v1(18.08,52.07)
A13: length 19.2
  TOP w0.127: 21.72,52.7 v1(18.62,52.7)
  BOTTOM w0.127: J1.18 8.66,59.92 13.18,59.92 15.21,57.89 15.21,54.99 17.5,52.7 v1(18.62,52.7)
A14: length 21.1
  TOP w0.127: 21.72,53.98 v1(17.04,53.98)
  BOTTOM w0.127: J1.19 8.92,62.2 14,62.2 17.04,59.16 v1(17.04,53.98)
A15: length 22.4
  TOP w0.127: 21.72,54.61 v1(18.08,54.61)
  BOTTOM w0.127: v1(18.08,54.61) 18.08,60.66 14,64.74 8.92,64.74 J1.20
A16: length 9.2
  TOP w0.127: U1.47 v1(19.25,26.03)
  BOTTOM w0.127: J1.37 14.6,26.03 v1(19.25,26.03)
A17: length 13.3
  TOP w0.127: U1.46 v1(22.73,26.67)
  BOTTOM w0.127: v1(22.73,26.67) 18.92,30.48 J1.38
A18: length 54.1
  TOP w0.127: U2.6 41.76,41.43 41.76,27.94 38.51,24.69 18.87,24.69 18.39,25.17 18.39,27.94 ; 18.39,27.94 U1.44 ; 18.39,27.94 17.78,27.94 J1.39
A19: length 52.2
  TOP w0.127: U1.43 v1(24.89,28.58) ; J1.40 15.21,38.07 15.21,41.91 16.48,43.18 v1(24.89,43.18) 26.11,43.18 28.65,45.72 U2.5
  BOTTOM w0.127: v1(24.89,28.58) v1(24.89,43.18)
A20: length 49.1
  TOP w0.127: U1.41 19.18,29.84 17.4,31.62 17.4,38 v1(17.5,38.1) ; U2.4 37.72,45.97 17.5,45.97 14.71,43.18 14.71,40.11 J1.41
  BOTTOM w0.127: v1(17.5,38.1) J1.41
A21: length 54.7
  TOP w0.127: U1.40 18.97,30.48 17.91,31.55 v1(17.91,32.31) ; U2.3 37.59,48.39 37.59,46.86 37.21,46.48 14.71,46.48 14.2,45.97 14.2,42.14 J1.42
  BOTTOM w0.127: v1(17.91,32.31) 18.92,32.31 19.94,33.32 19.94,38.35 17.65,40.64 J1.42
A22: length 54
  TOP w0.127: U1.38 v1(23.77,31.75) ; v1(20.19,42.67) 33.02,42.67 35.03,44.68 40.49,44.68 41.25,45.44 41.25,52.1 U2.2
  BOTTOM w0.127: v1(23.77,31.75) 22.73,31.75 20.19,34.29 v1(20.19,42.67) 19.68,43.18 J1.43
A23: length 59.2
  TOP w0.127: U1.37 v1(23.24,32.38) ; J1.44 13.72,46.74 36.58,46.74 37.08,47.24 37.08,52.96 U2.1
  BOTTOM w0.127: v1(23.24,32.38) 23.24,42.8 20.32,45.72 J1.44
AEN: length 65.6
  TOP w0.127: U2.8 36.47,41.63 v1(15.72,41.63)
  BOTTOM w0.127: v1(15.72,41.63) 7.65,41.63 6.12,43.15 6.12,58.39 7.14,59.41 13.18,59.41 13.94,58.65 13.94,54.58 J1.47
BA0: length 77
  TOP w0.127: U4.13 v1(32.77,81.28) ; U1.13 v1(32.13,33.02) ; U5.6 v1(46.99,94.11) ; U3.13 v1(32.77,55.24)
  BOTTOM w0.127: v1(46.99,94.11) 34.16,81.28 v1(32.77,81.28) 31.75,80.26 31.75,55.24 ; v1(32.13,33.02) 31.5,33.66 31.5,55.24 31.75,55.24 ; 31.75,55.24 v1(32.77,55.24)
BA1: length 89.3
  TOP w0.127: U1.14 v1(26.9,33.66) ; U5.7 v1(45.72,95) ; U3.14 v1(26.9,55.88) ; U4.14 v1(27.94,81.91)
  BOTTOM w0.127: v1(45.72,95) 45.08,95.63 34.04,95.63 27.94,89.53 v1(27.94,81.91) 26.9,80.87 v1(26.9,55.88) v1(26.9,33.66)
BA2: length 92.7
  TOP w0.127: v1(34.29,57.15) U3.16 29.18,57.15 v1(29.03,57) ; U4.16 v1(28.96,83.19) ; v1(34.29,31.52) 34.29,32.41 31.78,34.92 U1.16 ; U5.8 v1(44.45,95)
  BOTTOM w0.127: v1(34.29,31.52) v1(34.29,57.15) ; v1(29.03,57) 27.15,58.88 27.15,80.39 28.96,82.19 v1(28.96,83.19) 28.45,83.69 28.45,88.77 35.05,95.38 44.07,95.38 v1(44.45,95)
BA3: length 122.3
  TOP w0.127: U5.9 v1(43.18,94.87) ; v1(29.03,57.78) U3.17 43.54,57.78 44.81,56.52 44.81,53.82 46.58,52.04 47.85,52.04 48.62,51.28 48.62,45.19 47.85,44.42 39.62,44.42 38.76,43.56 38.76,42.8 39.52,42.04 40.03,42.04 41.25,40.82 41.25,32.79 40.49,32.03 37.08,32.03 33.55,35.56 U1.17 ; U4.17 v1(33.5,83.82)
  BOTTOM w0.127: v1(43.18,94.87) 38.61,94.87 36.07,92.33 36.07,90.07 33.5,87.5 ; v1(29.03,57.78) 28.7,58.12 28.7,65.53 29.97,66.8 29.97,83.19 28.68,84.48 28.68,86.97 29.21,87.5 33.5,87.5 ; v1(33.5,83.82) 33.5,87.5
BA4: length 57.3
  TOP w0.127: v1(27.91,67.56) 27.43,68.05 27.43,83.31 29.21,85.09 U4.19 ; U3.19 v1(27.91,59.05) v1(27.91,56.49) ; U1.19 v1(28.07,36.83)
  BOTTOM w0.127: v1(28.07,36.83) 28.07,41.38 28.73,42.04 28.73,45.39 27.91,46.2 v1(27.91,56.49) ; v1(27.91,67.56) v1(27.91,59.05)
BA5: length 55.7
  TOP w0.127: U3.20 v1(29.46,59.69) ; U1.20 v1(28.6,37.46) ; U4.20 v1(29.46,85.72)
  BOTTOM w0.127: v1(28.6,37.46) 28.32,37.74 28.32,41.02 28.98,41.68 28.98,46.96 28.96,46.99 28.96,53.09 29.97,54.1 29.97,59.18 v1(29.46,59.69) 28.96,60.2 28.96,61.21 29.46,61.72 29.72,61.72 30.23,62.23 30.23,84.96 v1(29.46,85.72)
BA6: length 68.8
  TOP w0.127: U3.22 v1(29.46,60.96) ; U1.22 31.6,38.73 32.38,37.95 v1(32.38,37.69) ; 31.11,87 v1(29.46,87)
  BOTTOM w0.127: v1(29.46,87) 30.76,85.7 30.76,60.96 ; v1(32.38,37.69) 32.64,37.44 32.64,32.77 32.38,32.51 31.37,32.51 30.76,33.12 30.76,60.96 ; 30.76,60.96 v1(29.46,60.96)
BA7: length 56.7
  TOP w0.127: U1.23 v1(32.13,39.37) ; U3.23 v1(32.77,61.59) ; U4.23 33.27,87.63 35.81,85.09 v1(35.81,79.5)
  BOTTOM w0.127: v1(32.13,39.37) 32.13,53.21 33.27,54.36 33.27,61.09 v1(32.77,61.59) 32.77,76.45 v1(35.81,79.5)
BD0: length 9.5
  TOP w0.127: U5.25 36.32,78.11 35.31,79.12 35.31,80.39 35.05,80.64 U4.12
BD1: length 8
  TOP w0.127: 38.81,79.38 v1(37.36,79.38) ; U4.11 v1(34.8,80.01)
  BOTTOM w0.127: v1(37.36,79.38) 36.73,80.01 v1(34.8,80.01)
BD2: length 14.1
  TOP w0.127: U4.9 34.29,78.74 35.43,77.6 40.11,77.6 40.39,77.88 40.39,80.39 40.13,80.64 U5.23
BD3: length 9.6
  TOP w0.127: v1(36.65,80.77) 37.8,81.91 U5.22 ; U4.8 v1(32.77,78.11)
  BOTTOM w0.127: v1(36.65,80.77) 34.8,80.77 32.77,78.74 v1(32.77,78.11)
BD4: length 39.2
  TOP w0.127: U5.21 38.3,83.19 36.86,84.63 36.86,86.74 37.62,87.5 40.36,87.5 42.65,85.22 42.65,77.6 40.11,75.06 37.74,75.06 36.86,74.17 36.86,73.91 36.09,73.15 29.82,73.15 29.69,73.28 29.69,76.58 29.95,76.83 U4.6
BD5: length 18.7
  TOP w0.127: U4.5 32.79,76.2 33.93,77.34 40.39,77.34 40.77,77.72 40.77,84.07 40.39,84.45 U5.20
BD6: length 19.6
  TOP w0.127: U5.19 v1(40.77,85.72) ; U4.3 33.45,74.93 33.81,75.29 v1(33.81,76.3)
  BOTTOM w0.127: v1(40.77,85.72) 40.77,80.72 36.35,76.3 v1(33.81,76.3)
BD7: length 23.2
  TOP w0.127: 38.81,87 40.13,87 41.53,85.6 41.53,77.44 40.41,76.33 37.59,76.33 35.56,74.3 U4.2
BD8: length 19.4
  TOP w0.127: U3.2 v1(29.46,48.26) ; U1.12 v1(28.83,32.38)
  BOTTOM w0.127: v1(28.83,32.38) 29.46,33.02 v1(29.46,48.26)
BD9: length 21
  TOP w0.127: U3.3 v1(32.77,48.89) ; U1.11 v1(32.38,31.75)
  BOTTOM w0.127: v1(32.38,31.75) 32.89,32.26 32.89,48.77 v1(32.77,48.89)
BD10: length 26.4
  TOP w0.127: U3.5 v1(27.41,50.16) ; U1.9 v1(27.84,30.48)
  BOTTOM w0.127: v1(27.41,50.16) 27.15,49.91 27.15,35.1 27.84,34.42 v1(27.84,30.48)
BD11: length 25
  TOP w0.127: U3.6 v1(29.46,50.8) ; U1.8 v1(28.78,29.84)
  BOTTOM w0.127: v1(28.78,29.84) 29.97,31.04 29.97,50.29 v1(29.46,50.8)
BD12: length 29.5
  TOP w0.127: U1.6 v1(33.78,28.58) ; U3.8 v1(33.78,52.07)
  BOTTOM w0.127: v1(33.78,52.07) v1(33.78,28.58)
BD13: length 29.3
  TOP w0.127: U1.5 v1(33.05,27.94) ; U3.9 v1(32.77,52.7)
  BOTTOM w0.127: v1(33.05,27.94) 33.27,28.17 33.27,52.2 v1(32.77,52.7)
BD14: length 36
  TOP w0.127: U3.11 v1(26.39,53.98) ; U1.3 v1(26.62,26.67)
  BOTTOM w0.127: v1(26.39,53.98) 26.39,26.9 v1(26.62,26.67)
BD15: length 36.6
  TOP w0.127: U1.2 v1(34.8,26.03) ; U3.12 v1(34.8,54.61)
  BOTTOM w0.127: v1(34.8,54.61) v1(34.8,26.03)
BNC2: length 12.9
  TOP w0.127: L1.2 115.57,33.02 J2.1
  BOTTOM w0.127: C5.1 J2.1
BNC3: length 11.8
  TOP w0.127: J3.1 117.35,13.97 115.39,12.01 114.88,12.01 L2.2
  BOTTOM w0.127: C6.1 J3.1
BRD: length 84.1
  TOP w0.127: U5.73 v1(51.31,93.34)
  BOTTOM w0.127: v1(51.31,93.34) 41.27,83.31 41.27,68.81 48.92,61.16 48.92,39.47 48.79,39.34 47.4,39.34 46.38,38.33 46.38,36.8 U2.16
BRESET: length 72.3
  TOP w0.127: v1(48.79,70.61) 48.79,88.65 43.84,93.6 41.3,93.6 40.28,94.61 U5.12
  BOTTOM w0.127: v1(48.79,70.61) 51.16,70.61 51.66,70.1 51.66,37.06 U2.15
BWR: length 51.1
  TOP w0.127: v1(50.9,70.1) 64.52,70.1 65.41,69.22 67.87,69.22
  BOTTOM w0.127: U2.17 48.36,38.1 50.9,40.64 v1(50.9,70.1)
D0: length 60.9
  TOP w0.127: 6.63,86.36 6.63,60.48 7.14,59.97 17.75,59.97 19.38,61.59 21.72,61.59 ; 6.63,86.36 J1.28 ; 6.63,86.36 6.63,87.4 6.98,87.76 7.9,87.76 8.61,88.47 9.47,88.47 10.9,89.89 17.5,89.89 19.76,87.63 21.72,87.63
D1: length 49.8
  TOP w0.127: 21.72,60.96 v1(25.17,60.96) ; v1(24.36,86.23) 23.6,87 21.72,87
  BOTTOM w0.127: v1(25.17,60.96) 25.17,85.42 v1(24.36,86.23) 23.44,85.32 9.12,85.32 J1.27
D2: length 45.4
  TOP w0.127: 21.72,85.72 20.22,85.72 v1(19.05,84.56) ; 21.72,59.69 21.84,59.82 v1(23.37,59.82)
  BOTTOM w0.127: J1.26 8.86,82.52 17.02,82.52 v1(19.05,84.56) 21.11,84.56 22.63,83.03 22.63,60.55 v1(23.37,59.82)
D3: length 55.2
  TOP w0.127: v1(25.93,72.87) 25.73,72.67 12.17,72.67 10.13,74.7 10.13,76.23 J1.25 ; 21.72,85.09 v1(25.93,85.09) ; 21.72,59.05 v1(23.57,59.05)
  BOTTOM w0.127: v1(25.93,85.09) v1(25.93,72.87) 25.93,60.91 24.08,59.05 v1(23.57,59.05)
D4: length 47
  TOP w0.127: 21.72,83.82 v1(20.04,83.82) ; 21.72,57.78 v1(23.37,57.78)
  BOTTOM w0.127: 20.04,83.06 v1(20.04,83.82) ; 20.04,83.06 20.29,83.06 22.12,81.23 22.12,59.03 v1(23.37,57.78) ; 20.04,83.06 19.79,83.06 19,82.27 12.17,82.27 10.13,80.24 10.13,78.71 J1.24
D5: length 50
  TOP w0.127: 21.72,57.15 20.45,57.15 19.56,58.04 v1(19.56,61.06) ; 21.72,83.19 23.9,83.19 26.44,80.64 26.44,72.16 24.16,69.88 v1(19.56,69.88)
  BOTTOM w0.127: v1(19.56,61.06) v1(19.56,69.88) 11.4,69.88 J1.23
D6: length 45.9
  TOP w0.127: J1.22 8.61,72.11 v1(23.37,72.11) ; 21.72,81.91 v1(23.37,81.91) ; v1(24.31,60.32) 24.31,57.4 22.78,55.88 21.72,55.88
  BOTTOM w0.127: v1(24.31,60.32) 23.37,61.26 v1(23.37,72.11) v1(23.37,81.91)
D7: length 50.8
  TOP w0.127: 21.72,81.28 v1(18.77,81.28) ; 21.72,55.24 v1(19.28,55.24)
  BOTTOM w0.127: v1(19.28,55.24) 19.02,55.5 19.02,64.74 16.48,67.28 8.92,67.28 J1.21 6.38,69.82 6.38,74.04 7.39,75.06 15.09,75.06 18.77,78.74 v1(18.77,81.28)
DATA: length 10.8
  TOP w0.127: U7.1 29.84,93.29 31.06,92.08 38.81,92.08
DCLK: length 14.1
  TOP w0.127: U5.10 41.91,95.25 41.88,95.22 31.78,95.22 U7.2
DDIR: length 97.6
  TOP w0.127: U3.48 v1(23.37,47.62) 23.88,47.12 33.83,47.12 36.37,49.66 36.37,54.33 38.91,56.87 41,56.87 42.52,55.35 42.52,50.83 U2.20 ; U4.48 v1(20.07,73.66) ; U1.48 v1(26.11,25.4)
  BOTTOM w0.127: v1(20.07,73.66) 21.36,72.36 21.36,49.63 v1(23.37,47.62) 26.11,44.88 v1(26.11,25.4)
DEN: length 79.8
  TOP w0.127: U1.1 v1(35.84,25.4) ; U4.1 v1(35.84,73.66)
  BOTTOM w0.127: U2.21 48.62,47.27 48.62,40.16 48.11,39.65 35.84,39.65 ; v1(35.84,73.66) 35.84,39.65 ; 35.84,39.65 v1(35.84,25.4)
DHEN: length 28.5
  TOP w0.127: U2.22 46.33,50.8 43.79,53.34 43.79,56.11 42.77,57.12 36.12,57.12 35.61,56.62 35.61,50.16 33.07,47.62 U3.1
FPGA: length 35.7
  TOP w0.127: U5.30 v1(40.46,71.75)
  BOTTOM w0.127: U2.18 43.46,44.81 43.46,60.73 40.46,63.73 v1(40.46,71.75)
GAIN: length 111.6
  TOP w0.127: U23.6 v1(96.24,19.05) ; 38.81,74.3 40.08,74.3 41.22,73.15 41.22,71.25 39.95,69.98 37.95,69.98 37.59,69.62 37.59,68.73 37.72,68.61 44.96,68.61 45.21,68.35 45.21,66.09 45.72,65.58 48.26,65.58 49.28,64.57 49.28,54.41 60.4,43.28 78.59,43.28 83.13,38.73 v1(95.68,38.73) U19.6
  BOTTOM w0.127: v1(95.68,38.73) 95.68,19.61 v1(96.24,19.05)
HS: length 34.8
  TOP w0.127: U5.29 v1(40.46,73.02)
  BOTTOM w0.127: v1(40.46,73.02) 40.97,72.52 40.97,66.19 41.15,66.01 41.68,66.01 43.71,63.98 43.71,47.09 U2.19
MCLK: length 28
  TOP w0.127: U5.31 32.87,70.48 28.42,66.04 J1.52
MRD: length 51.5
  TOP w0.127: U2.9 37.74,35.56 32.79,40.51 18.01,40.51 16.74,39.24 16.74,36.86 14.2,34.32 11.96,34.32 11.2,35.08 11.2,49.3 J1.46
MWR: length 53.5
  TOP w0.127: U2.10 41,34.01 41,35.97 40.16,36.8 38.63,36.8 36.6,38.84 36.6,39.75 35.59,40.77 16.51,40.77 16.26,40.51 16.26,37.11 13.72,34.57 12.22,34.57 11.71,35.08 11.71,47.27 J1.45
N00036_DATA_DAAMP: length 47.6
  TOP w0.127: U18.5 87.05,34.29 86.79,34.54 86.79,35.76 87.1,36.07 89.1,36.07 89.48,36.45 89.48,36.7 ; U19.5 98.6,40 99.11,39.5 99.11,38.35 98.86,38.1 89.48,38.1 ; L4.2 104.01,27.94 101.47,30.48 v1(101.47,33.02) 101.47,34.42 99.19,36.7 89.48,36.7 ; 89.48,36.7 89.48,38.1 ; 89.48,38.1 U18.8
  BOTTOM w0.127: R16.1 v1(101.47,33.02) 101.47,31.62 R15.1
N00036_DATA_DAAMP0: length 41.9
  TOP w0.127: U21.8 90.68,17.78 90.86,17.6 90.86,16.26 90.45,15.85 87.78,15.85 87.43,15.49 87.43,14.22 87.68,13.97 U21.5 95.73,13.97 ; U23.5 96.62,20.32 95.73,19.43 95.73,13.97 ; 95.73,13.97 v1(102.74,13.97)
  BOTTOM w0.127: R17.1 v1(102.74,13.97) 102.74,11.43 ; L6.2 105.92,8.25 102.74,11.43 ; 102.74,11.43 R18.1
N00038_DATA_DAAMP: length 29.2
  TOP w0.127: L3.2 96.47,24.77 93.29,27.94 93.29,30.48 90.75,33.02 U18.4 85.29,33.02 v1(83.82,34.49)
  BOTTOM w0.127: C24.1 v1(83.82,34.49)
N00038_DATA_DAAMP0: length 27.5
  TOP w0.127: v1(84.45,14.17) 85.93,12.7 U21.4 99.06,12.7 L5.2
  BOTTOM w0.127: C27.1 v1(84.45,14.17)
N00044_DATA_DAAMP: length 33.6
  TOP w0.127: U19.1 102.87,31.22 104.88,29.21 114.3,29.21 114.94,28.58 114.94,15.98 114.3,15.34 U20.2
N00044_DATA_DAAMP0: length 25.5
  TOP w0.127: U23.1 v1(105.11,16.51)
  BOTTOM w0.127: v1(105.11,16.51) 105.11,31.47 106.88,33.25 110.39,33.25 111.66,34.52 U22.2
N00060_DATA_DAAMP: length 37.1
  TOP w0.127: U18.6 90.81,35.56 99.97,26.39 110.36,26.39 114.05,22.71 114.05,18.16 U20.3
N00060_DATA_DAAMP0: length 41.7
  TOP w0.127: U21.6 90.86,15.24 93.4,17.78 93.4,20.07 95.94,22.61 v1(111.43,22.61)
  BOTTOM w0.127: v1(111.43,22.61) 111.43,32.49 112.55,33.6 112.55,35.7 112.4,35.85 U22.3
N282866_DATA_DAAMP: length 5.3
  TOP w0.127: U19.8 v1(96.44,36.2)
  BOTTOM w0.127: v1(96.44,36.2) 96.44,34.62 R16.2
N282866_DATA_DAAMP0: length 3.1
  TOP w0.127: U23.8 97.89,15.95 v1(98.43,15.42)
  BOTTOM w0.127: v1(98.43,15.42) 98.43,14.86 R17.2
N282912_DATA_DAAMP: length 9.9
  TOP w0.127: U19.2 v1(101.32,37.46)
  BOTTOM w0.127: R15.2 99.19,31.62 99.19,35.33 v1(101.32,37.46)
N282912_DATA_DAAMP0: length 9.1
  TOP w0.127: U23.2 v1(100.63,17.78)
  BOTTOM w0.127: v1(100.63,17.78) 100.63,12.75 R18.2
NCS: length 14.9
  TOP w0.127: 29.84,102.23 30.86,101.22 38.86,101.22 40.64,99.44 U5.11
OE: length 45.7
  TOP w0.127: 29.84,99.69 28.6,98.45 28.6,93.85 30.89,91.57 40.61,91.57 43.15,89.03 43.15,71.5 40.87,69.22 38.81,69.22
OUTA: length 13.3
  BOTTOM w0.127: U20.6 108.69,28.47 L1.1
OUTB: length 34.3
  BOTTOM w0.127: L2.1 104.34,13.77 104.34,39.75 105.36,40.77 105.92,40.77 U22.6
POD_A+: length 20.5
  TOP w0.127: U1.26 v1(22.73,39.37)
  BOTTOM w0.127: J1.11 8.61,44.17 20.19,44.17 22.73,41.63 v1(22.73,39.37)
POD_A-: length 14.3
  TOP w0.127: U1.27 18.36,38.73 v1(17.75,39.34)
  BOTTOM w0.127: v1(17.75,39.34) 8.92,39.34 J1.10
POD_B+: length 14
  TOP w0.127: U1.29 v1(18.54,37.46)
  BOTTOM w0.127: J1.9 8.61,37.11 18.19,37.11 v1(18.54,37.46)
POD_B-: length 14
  TOP w0.127: U1.30 v1(19.43,36.83)
  BOTTOM w0.127: v1(19.43,36.83) 8.89,36.83 J1.8
POD_C+: length 14.5
  TOP w0.127: U1.32 v1(17.91,35.56)
  BOTTOM w0.127: v1(17.91,35.56) 14.45,35.56 13.16,34.26 8.86,34.26 J1.7
POD_C-: length 15.3
  TOP w0.127: U1.33 v1(19.43,34.92)
  BOTTOM w0.127: v1(19.43,34.92) 16.13,34.92 13.18,31.98 9.12,31.98 J1.6
POD_D+: length 15.8
  TOP w0.127: U1.35 v1(19.43,33.66)
  BOTTOM w0.127: J1.5 11.4,31.72 15.82,31.72 17.75,33.66 v1(19.43,33.66)
POD_D-: length 17.8
  TOP w0.127: U1.36 v1(18.44,33.02)
  BOTTOM w0.127: J1.4 10.9,28.68 10.9,30.2 12.17,31.47 16.71,31.47 17.25,32 17.25,32.51 17.75,33.02 v1(18.44,33.02)
Q0: length 7.3
  TOP w0.127: U6.12 R4.1
Q1: length 32
  TOP w0.127: R4.2 D4.2
Q2: length 7.3
  TOP w0.127: U6.14 R3.1
Q3: length 25
  TOP w0.127: R3.2 D3.2
Q4: length 7.3
  TOP w0.127: U6.16 R2.1
Q5: length 18
  TOP w0.127: R2.2 D2.2
Q6: length 7.3
  TOP w0.127: U6.18 R1.1
Q7: length 10.4
  TOP w0.127: R1.2 D1.2
RA0: length 132.8
  TOP w0.127: U12.5 v1(106.68,63.68) ; U14.5 81.91,75.87 v1(81.41,76.38) ; v1(81.91,79.65) 82.12,79.86 v1(107.19,79.86) ; U13.5 v1(81.91,89.08) ; U15.5 v1(81.91,101.98) ; v1(107.19,98.88) 106.68,99.39 U11.5 ; U10.5 v1(81.91,63.68) ; v1(107.19,89.08) 106.68,88.57 U17.5 ; v1(81.41,65.3) 73.48,65.3 70.84,67.95 70.84,73.3 70.26,73.89 70.23,73.89 69.8,74.3 67.87,74.3 ; U16.5 v1(106.68,76.38)
  BOTTOM w0.127: v1(106.68,76.38) 107.19,76.38 ; 107.19,76.38 v1(107.19,79.86) v1(107.19,89.08) v1(107.19,98.88) ; 107.19,76.38 107.19,64.19 v1(106.68,63.68) ; v1(81.91,63.68) 81.91,64.8 v1(81.41,65.3) v1(81.41,76.38) 81.91,76.89 v1(81.91,79.65) v1(81.91,89.08) v1(81.91,101.98)
RA1: length 128.5
  TOP w0.127: v1(80.14,65.81) 75.01,65.81 71.6,69.22 71.6,74.3 69.06,76.83 U5.60 ; 80.64,87.63 v1(80.64,89.08) ; 80.64,62.23 v1(80.64,63.68) ; U16.4 v1(105.41,76.38) ; v1(80.14,76.38) 80.64,75.87 80.64,74.93 ; U12.4 v1(105.41,63.68) ; 80.64,100.33 v1(80.64,98.7) v1(105.41,98.7) U11.4 ; U17.4 v1(105.41,89.59)
  BOTTOM w0.127: v1(105.41,98.7) v1(105.41,89.59) 105.92,89.08 105.92,79.78 105.41,79.27 v1(105.41,76.38) 105.92,75.87 105.92,64.19 v1(105.41,63.68) ; v1(80.64,98.7) v1(80.64,89.08) 80.14,88.57 v1(80.14,76.38) v1(80.14,65.81) 80.64,65.3 v1(80.64,63.68)
RA2: length 140.5
  TOP w0.127: U5.61 70.84,78.11 72.36,76.58 72.36,68.86 74.9,66.32 v1(79.38,66.32) v1(104.65,66.32) 106.17,66.32 108.46,64.03 108.46,61.01 104.85,61.01 104.14,61.72 U12.3 ; U15.3 v1(79.38,98.68) ; U16.3 v1(104.14,76.38) ; U10.3 v1(79.38,63.68) ; U13.3 v1(79.38,89.08) ; U14.3 v1(79.38,76.38) ; U11.3 v1(104.14,101.78) ; U17.3 v1(104.14,89.08)
  BOTTOM w0.127: v1(79.38,98.68) 79.88,98.17 79.88,89.59 v1(79.38,89.08) v1(79.38,76.38) v1(79.38,66.32) v1(79.38,63.68) ; v1(104.14,101.78) v1(104.14,89.08) v1(104.14,76.38) 104.65,75.87 v1(104.65,66.32)
RA3: length 123.8
  TOP w0.127: U16.2 v1(102.87,76.38) ; U11.2 v1(102.87,101.78) ; 78.1,100.33 78.1,101.27 v1(77.6,101.78) ; 67.87,79.38 v1(72.47,79.38) ; U17.2 v1(102.87,89.08) ; 78.1,87.63 v1(78.1,89.28) ; U12.2 v1(102.87,63.68) ; 78.1,62.23 v1(78.1,63.68) ; v1(78.1,78.51) v1(102.87,78.51) ; 78.1,74.93 v1(78.1,76.38)
  BOTTOM w0.127: 77.6,89.28 v1(77.6,101.78) ; 77.6,89.28 77.6,79.38 ; 77.6,89.28 v1(78.1,89.28) ; 77.6,79.38 77.6,79.02 v1(78.1,78.51) v1(78.1,76.38) v1(78.1,63.68) ; 77.6,79.38 v1(72.47,79.38) ; v1(102.87,101.78) v1(102.87,89.08) v1(102.87,78.51) v1(102.87,76.38) 103.38,75.87 103.38,64.19 v1(102.87,63.68)
RA4: length 122.5
  TOP w0.127: U12.32 v1(101.6,70.31) ; U17.32 v1(101.6,95.71) ; v1(101.6,83.01) U16.32 v1(101.6,85.9) 77.77,85.9 76.84,84.96 U14.32 v1(76.84,83.01) ; v1(70.33,80.92) 70.33,80.64 ; 70.33,80.64 73.23,80.64 73.48,80.39 73.48,72.97 75.62,72.97 U10.32 ; 70.33,80.64 U5.63 ; U11.32 v1(101.6,108.36) ; U15.32 v1(76.84,108.41) ; U13.32 v1(76.84,95.71)
  BOTTOM w0.127: v1(70.33,80.92) 72.42,83.01 v1(76.84,83.01) v1(76.84,95.71) v1(76.84,108.41) ; v1(101.6,70.31) v1(101.6,83.01) ; v1(101.6,108.36) v1(101.6,95.71) v1(101.6,85.9)
RA5: length 141.4
  TOP w0.127: 78.1,71.75 78.1,71.25 77.39,70.54 75.51,70.54 73.23,72.82 73.23,79.38 72.47,80.14 66.65,80.14 66.65,81.91 ; U12.31 v1(102.87,70.31) ; U17.31 102.87,96.22 v1(102.36,95.71) ; v1(102.36,81.61) 101.63,80.87 v1(78.1,80.87) 77.09,80.87 73,84.96 66.65,84.96 66.65,81.91 ; U16.31 102.87,83.52 v1(102.36,83.01) ; U11.31 v1(102.87,108.05) ; 66.65,81.91 U5.64 ; 78.1,97.16 v1(78.1,95.71) ; 78.1,84.45 v1(78.1,83.01) ; 78.1,109.86 v1(78.1,107.57)
  BOTTOM w0.127: v1(78.1,80.87) v1(78.1,83.01) 78.61,83.52 78.61,95.71 ; v1(78.1,95.71) 78.61,95.71 ; 78.61,95.71 78.61,107.06 v1(78.1,107.57) ; v1(102.87,108.05) 102.36,107.54 v1(102.36,95.71) v1(102.36,83.01) v1(102.36,81.61) 102.36,70.82 v1(102.87,70.31)
RA6: length 136.9
  TOP w0.127: U12.30 v1(104.14,70.31) 103.63,69.8 101.04,69.8 100.33,70.51 98.12,70.51 97.41,69.8 91.06,69.8 90.3,70.56 90.3,72.72 89.79,73.23 83.69,73.23 83.69,70.31 83.19,69.8 80.82,69.8 79.38,71.25 U10.30 79.38,72.26 78.41,73.23 74.78,73.23 73.76,74.24 73.76,79.86 ; 73.76,79.86 73.76,80.64 71.22,83.19 U5.65 ; 73.76,79.86 v1(78.87,79.86) ; v1(103.63,95.71) 104.14,96.22 U17.30 ; U11.30 104.14,108.76 v1(103.63,108.25) ; U15.30 v1(79.38,107.31) ; v1(78.87,82.5) 79.38,83.01 U14.30 ; U16.30 104.14,83.52 v1(103.63,83.01) ; U13.30 v1(79.38,95.71)
  BOTTOM w0.127: v1(103.63,108.25) v1(103.63,95.71) v1(103.63,83.01) 103.63,70.82 v1(104.14,70.31) ; v1(79.38,95.71) 78.87,95.71 ; 78.87,95.71 v1(78.87,82.5) v1(78.87,79.86) ; 78.87,95.71 78.87,106.81 v1(79.38,107.31)
RA7: length 132.7
  TOP w0.127: U12.29 v1(105.41,70.05) ; v1(104.9,102.51) 105.92,101.5 105.92,97.08 105.79,96.95 105.54,96.95 105.41,97.08 U17.29 ; v1(104.9,80.37) v1(81.41,80.37) 75.54,80.37 74.27,81.64 74.27,83.19 73,84.45 U5.66 ; 80.64,109.86 80.64,108.03 v1(81.36,107.31) ; U11.29 v1(105.41,108.36) ; 80.64,71.75 v1(80.64,73.41) ; 80.64,97.16 80.64,96.42 v1(81.36,95.71) ; v1(80.64,83.01) 80.64,84.45 ; U16.29 v1(105.41,83.01)
  BOTTOM w0.127: v1(105.41,70.05) 104.9,70.56 v1(104.9,80.37) 104.9,83.01 ; v1(105.41,83.01) 104.9,83.01 ; 104.9,83.01 v1(104.9,102.51) 105.41,103.02 v1(105.41,108.36) ; 81.36,83.01 v1(81.36,95.71) v1(81.36,107.31) ; 81.36,83.01 v1(80.64,83.01) ; 81.36,83.01 81.41,83.01 v1(81.41,80.37) 80.64,79.6 v1(80.64,73.41)
RA8: length 139.1
  TOP w0.127: U17.28 106.68,98.12 106.17,98.63 v1(106.17,103.02) ; U14.28 81.91,82.75 v1(82.68,81.99) ; U11.28 v1(106.68,108.36) ; U10.28 v1(81.91,73.41) ; U5.67 v1(69.82,85.72) ; U15.28 v1(81.91,107.85) ; U13.28 81.91,94.84 v1(82.68,94.08) ; U16.28 v1(106.68,83.01) ; U12.28 v1(106.68,70.05) ; v1(74.78,78.87) 75.06,79.15 v1(82.68,79.15) 82.8,79.27 v1(106.17,79.27)
  BOTTOM w0.127: v1(74.78,78.87) 71.6,78.87 69.82,80.64 v1(69.82,85.72) ; v1(106.68,108.36) 106.68,103.53 v1(106.17,103.02) 106.17,83.01 ; v1(106.68,70.05) 106.17,70.56 v1(106.17,79.27) 106.17,83.01 ; 106.17,83.01 v1(106.68,83.01) ; v1(81.91,107.85) 82.68,107.09 v1(82.68,94.08) v1(82.68,81.99) v1(82.68,79.15) 82.68,74.17 v1(81.91,73.41)
RA9: length 140.6
  TOP w0.127: U14.22 89.53,83.52 v1(89.03,83.01) ; U13.22 89.53,96.22 v1(89.03,95.71) ; U12.22 v1(114.3,70.31) ; U17.22 v1(114.3,95.71) ; U16.22 v1(114.3,83.01) 113.41,82.12 98.15,82.12 97.41,81.38 v1(89.03,81.38) 77.57,81.38 76.05,82.91 76.05,85.45 73.23,88.27 U5.69 ; U15.22 v1(89.53,108.36) ; U10.22 v1(89.53,70.05) ; U11.22 v1(114.3,108.41)
  BOTTOM w0.127: v1(89.53,70.05) 89.03,70.56 v1(89.03,81.38) v1(89.03,83.01) v1(89.03,95.71) 89.53,96.22 v1(89.53,108.36) ; v1(114.3,108.41) v1(114.3,95.71) v1(114.3,83.01) v1(114.3,70.31)
RA10: length 143.8
  TOP w0.127: U16.21 v1(115.57,83.01) ; U11.21 v1(115.57,108.41) ; U17.21 v1(115.57,95.71) ; U13.21 v1(90.81,95.71) ; v1(90.81,73.2) U10.21 90.93,71.75 91.57,73.46 91.82,73.71 117.86,73.71 118.62,72.95 118.62,70.66 117.55,69.6 116.28,69.6 v1(115.57,70.31) U12.21 ; U14.21 v1(90.81,83.01) ; U15.21 v1(90.81,108.36) ; U5.70 70.59,89.53 71.37,90.32 90.42,90.32 v1(90.81,90.7)
  BOTTOM w0.127: v1(90.81,108.36) v1(90.81,95.71) v1(90.81,90.7) v1(90.81,83.01) v1(90.81,73.2) ; v1(115.57,70.31) v1(115.57,83.01) v1(115.57,95.71) v1(115.57,108.41)
RA11: length 134.5
  TOP w0.127: U14.20 v1(92.07,83.01) ; U12.20 v1(116.84,70.1) ; U15.20 v1(92.07,108.36) ; U16.20 v1(116.84,83.01) ; U10.20 v1(92.07,73.2) ; 116.33,105.05 v1(92.07,105.05) ; 116.33,105.05 116.84,105.56 U11.20 ; 116.33,105.05 116.33,96.22 v1(116.84,95.71) U17.20 ; U13.20 v1(92.07,95.71) ; v1(92.07,91.21) 89.03,91.21 88.42,90.6 69.09,90.6 68.88,90.8 U5.71
  BOTTOM w0.127: v1(92.07,73.2) v1(92.07,83.01) v1(92.07,91.21) v1(92.07,95.71) v1(92.07,105.05) v1(92.07,108.36) ; v1(116.84,70.1) v1(116.84,83.01) v1(116.84,95.71)
RA12: length 149.4
  TOP w0.127: 93.34,73.2 v1(117.6,73.2) 118.11,72.69 U12.19 ; 93.34,73.2 v1(92.84,73.2) ; 93.34,73.2 93.34,71.75 ; v1(92.84,83.01) 93.34,83.52 93.34,84.45 ; v1(70.36,95.22) 65.48,95.22 64.77,95.94 U5.76 ; U11.19 118.11,103.07 117.6,102.57 v1(117.6,95.71) 118.11,96.22 U17.19 ; U16.19 118.11,83.52 v1(117.6,83.01) ; v1(92.84,108.41) 93.34,108.92 93.34,109.86 ; 93.34,97.16 93.34,96.22 v1(92.84,95.71)
  BOTTOM w0.127: v1(92.84,73.2) v1(92.84,83.01) v1(92.84,95.71) v1(92.84,108.41) 91.82,109.42 74.4,109.42 70.36,105.38 v1(70.36,95.22) ; v1(117.6,95.71) v1(117.6,83.01) v1(117.6,73.2)
RA13: length 167.8
  TOP w0.127: U11.18 119.38,102.51 118.87,102.01 118.87,98.81 ; U5.77 v1(63.5,97.89) ; 118.87,98.81 119.38,98.3 U17.18 ; 118.87,98.81 118.87,83.19 v1(119.38,82.68) U16.18 ; v1(94.11,70.31) 94.62,70.82 U10.18 ; U13.18 v1(94.62,95.66) ; v1(94.11,82.98) 94.62,83.49 U14.18 ; v1(94.11,108.41) 94.62,108.92 U15.18 ; U12.18 v1(119.38,70.31)
  BOTTOM w0.127: 94.11,95.66 v1(94.11,82.98) v1(94.11,70.31) 94.11,63.93 95.12,62.92 118.11,62.92 119.38,64.19 v1(119.38,70.31) v1(119.38,82.68) ; 94.11,95.66 v1(94.11,108.41) 92.84,109.68 72.75,109.68 63.5,100.43 v1(63.5,97.89) ; 94.11,95.66 v1(94.62,95.66)
RA14: length 171.6
  TOP w0.127: U14.15 94.62,75.87 v1(95.12,76.38) ; 119.38,61.01 119.89,61.01 119.89,75.87 ; 119.38,61.01 U12.15 ; 119.38,61.01 117.86,59.49 95.63,59.49 95.12,59.99 ; v1(95.12,89.59) 94.62,89.08 U13.15 ; U16.15 119.38,75.62 119.63,75.87 119.89,75.87 ; 119.89,89.66 119.38,89.15 U17.15 ; 119.89,89.66 119.89,75.87 ; 119.89,89.66 119.89,98.55 119.38,99.06 U11.15 ; U10.15 94.62,60.25 94.87,59.99 95.12,59.99 ; v1(95.71,92.23) 95.61,92.13 79.25,92.13 75.31,96.06 75.31,98.6 75.06,98.86 58.17,98.86 57.91,98.6 57.91,95.35 58.93,94.34 60.63,94.34 62.23,95.94 U5.78 ; U15.15 v1(94.62,101.78) ; 95.12,59.99 v1(95.12,63.68)
  BOTTOM w0.127: v1(95.12,63.68) v1(95.12,76.38) v1(95.12,89.59) 95.12,91.64 v1(95.71,92.23) 95.71,100.69 v1(94.62,101.78)
RA15: length 151.9
  TOP w0.127: 93.34,62.23 v1(93.34,63.68) ; v1(60.96,101.8) 69.85,101.8 70.33,102.29 80.39,102.29 81.41,101.27 81.41,99.11 92.63,99.11 93.34,99.82 v1(93.34,101.78) ; U12.14 v1(118.11,63.68) ; U11.14 118.11,99.14 118.62,98.63 118.62,90.78 118.11,90.27 ; 118.11,90.27 94.54,90.27 v1(93.34,89.08) 93.34,87.63 ; 118.11,90.27 v1(118.11,89.08) U17.14 ; 93.34,74.93 v1(93.34,76.38) ; U16.14 v1(118.11,76.38) ; U5.79 v1(60.96,98.09)
  BOTTOM w0.127: v1(93.34,63.68) v1(93.34,76.38) v1(93.34,89.08) v1(93.34,101.78) ; v1(118.11,89.08) v1(118.11,76.38) v1(118.11,63.68) ; v1(60.96,98.09) v1(60.96,101.8)
RCS0: length 42.4
  TOP w0.127: v1(83.19,63.68) 83.19,60.71 82.68,60.2 65.96,60.2 65.71,60.45 64.08,60.45 59.69,64.85 U5.48 ; 83.19,74.93 v1(83.19,73.28)
  BOTTOM w0.127: v1(83.19,73.28) v1(83.19,63.68)
RCS1: length 86.9
  TOP w0.127: v1(62.23,69.09) 61.21,69.09 60.96,68.83 U5.49 ; 83.19,100.33 83.19,102.54 ; 83.19,102.54 84.18,103.53 106.43,103.53 107.95,102.01 U11.6 ; 83.19,102.54 v1(62.23,102.54)
  BOTTOM w0.127: v1(62.23,102.54) v1(62.23,69.09)
RCS2: length 64
  TOP w0.127: U16.6 v1(107.95,76.58) ; U12.6 v1(107.95,63.68) 107.39,64.24 64.77,64.24 62.23,66.78 U5.50
  BOTTOM w0.127: v1(107.95,63.68) 107.44,64.19 107.44,76.07 v1(107.95,76.58)
RCS3: length 75.6
  TOP w0.127: 83.19,86.41 83.19,86.16 100.08,86.16 100.33,86.41 107.87,86.41 107.95,86.49 U17.6 ; 83.19,86.41 77.6,86.41 77.6,88.6 77.34,88.85 75.56,88.85 75.49,88.77 66.65,88.77 66.4,88.52 66.4,71.55 66.7,71.25 68.73,71.25 69.09,70.89 69.09,68.83 68.86,68.61 63.53,68.61 63.5,68.58 U5.51 ; 83.19,86.41 83.19,87.63
RD0: length 102.9
  TOP w0.127: U16.26 109.22,85.65 v1(109.73,86.16) ; U17.26 v1(109.22,95.45) ; U15.26 v1(84.45,108.05) ; v1(109.22,93.09) 107.85,91.72 86.33,91.72 v1(86.23,91.62) 77.34,91.62 70.36,98.6 59.23,98.6 58.42,97.79 U5.81 ; U14.26 84.45,83.19 85.67,81.97 v1(87.25,81.97)
  BOTTOM w0.127: v1(109.73,86.16) 109.73,92.58 v1(109.22,93.09) v1(109.22,95.45) ; v1(84.45,108.05) 86.23,106.27 v1(86.23,91.62) 87.5,90.35 87.5,82.22 v1(87.25,81.97)
RD1: length 116.4
  TOP w0.127: U14.23 88.27,82.93 88.72,82.47 v1(91.34,82.47) ; v1(91.34,94.89) 112.22,94.89 v1(113.03,95.71) U17.23 ; U15.23 88.27,108.92 v1(88.77,108.41) ; U5.82 57.15,99.11 57.91,99.87 v1(75.29,99.87) ; U16.23 v1(113.03,82.98)
  BOTTOM w0.127: 88.77,108.92 v1(88.77,108.41) ; 88.77,108.92 91.06,108.92 91.34,108.64 v1(91.34,94.89) v1(91.34,82.47) ; 88.77,108.92 76.56,108.92 75.29,107.65 v1(75.29,99.87) ; v1(113.03,82.98) v1(113.03,95.71)
